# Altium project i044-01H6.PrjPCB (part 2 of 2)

## Sheet M_SSD128_HD_8_95Vin_5Vout_1500mA_LowProfile.SchDoc
size A4; Organization: Ingenia Drives - Novanta; Address1: Carrer Avila, 124, 2B; Address2: 08018 Barcelona Spain; Address3: www.ingeniamc.com; Address4: www.ingeniamc.com; DocumentNumber: 8; Revision: i044-01H6-1.2.3; SheetNumber: 8; SheetTotal: 8
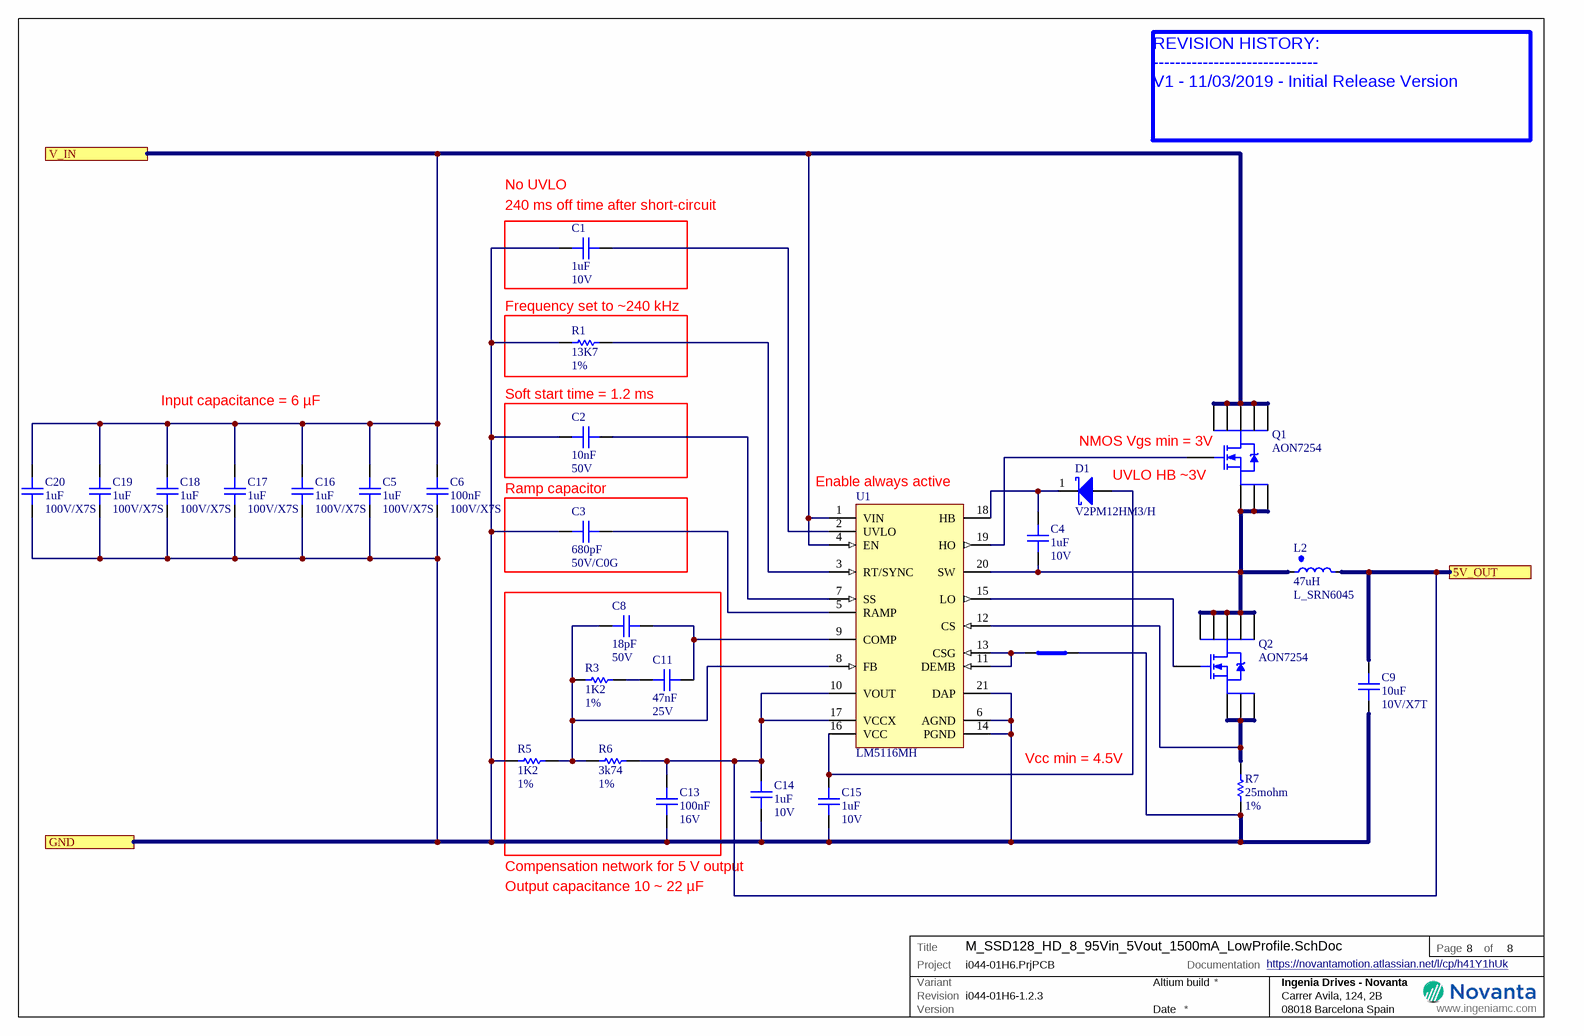
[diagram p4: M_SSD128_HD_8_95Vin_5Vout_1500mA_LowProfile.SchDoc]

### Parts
(Parts that share a designator on the sheet are numbered #1, #2 ... from top to bottom, then left to right.)
C1#2  value 1uF  Voltage: 10V  [C_0402HD]  (hidden comment: C_0402--1uF--10V)
C2#2  value 10nF  Voltage: 50V  [C_0402HD]  (hidden comment: C_0402--10nF--50V)
C3#2  value 680pF  Voltage: 50V/C0G  [C_0402HD]  (hidden comment: C_0402--680pF--50V/C0G)
C4#2  value 1uF  Voltage: 10V  [C_0402HD]  (hidden comment: C_0402--1uF--10V)
C5#2  value 1uF  Voltage: 100V/X7S  [C_0805_1.45mm]  (hidden comment: C_0805--1uF--100V/X7S)
C6#2  value 100nF  Voltage: 100V/X7S  [C_0603]  (hidden comment: C_0603--100nF--100V/X7S)
C8#2  value 18pF  Voltage: 50V  [C_0402HD]  (hidden comment: C_0402--18pF--50V)
C9#2  value 10uF  Voltage: 10V/X7T  [C_0603]  (hidden comment: C_0603--10uF--10V/X7T)
C11#2  value 47nF  Voltage: 25V  [C_0402HD]  (hidden comment: C_0402--47nF--25V)
C13#2  value 100nF  Voltage: 16V  [C_0402HD]  (hidden comment: C_0402--100nF--16V)
C14#2  value 1uF  Voltage: 10V  [C_0402HD]  (hidden comment: C_0402--1uF--10V)
C15#2  value 1uF  Voltage: 10V  [C_0402HD]  (hidden comment: C_0402--1uF--10V)
C16#2  value 1uF  Voltage: 100V/X7S  [C_0805_1.45mm]  (hidden comment: C_0805--1uF--100V/X7S)
C17#2  value 1uF  Voltage: 100V/X7S  [C_0805_1.45mm]  (hidden comment: C_0805--1uF--100V/X7S)
C18  value 1uF  Voltage: 100V/X7S  [C_0805_1.45mm]  (hidden comment: C_0805--1uF--100V/X7S)
C19#2  value 1uF  Voltage: 100V/X7S  [C_0805_1.45mm]  (hidden comment: C_0805--1uF--100V/X7S)
C20  value 1uF  Voltage: 100V/X7S  [C_0805_1.45mm]  (hidden comment: C_0805--1uF--100V/X7S)
D1#2  V2PM12HM3/H  [MicroSMP]
L2#2  value 47uH  [L_SRN6045]  (hidden comment: L_SRN6045--47uH)
NT1  NT_TOP_1.2x0.2  [NETTIE-TOP]  (value not drawn)  (net tie, no BOM)
Q1#2  AON7254  [8-PowerWDFN(3.3x3.3)]
Q2#2  AON7254  [8-PowerWDFN(3.3x3.3)]
R1#2  value 13K7  Tolerance: 1%  [R_0402HD]  (hidden comment: R_0402--13K7--1%)
R3#2  value 1K2  Tolerance: 1%  [R_0402HD]  (hidden comment: R_0402--1K2--1%)
R5#2  value 1K2  Tolerance: 1%  [R_0402HD]  (hidden comment: R_0402--1K2--1%)
R6#2  value 3k74  Tolerance: 1%  [R_0402HD]  (hidden comment: R_0402--3k74--1%)
R7#2  value 25mohm  Tolerance: 1%  [R_0603]  (hidden comment: R_0603--25mohm--1%)
U1#2  LM5116MH  [TSOP20_065P_EP]

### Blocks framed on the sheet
240 ms off time after short-circuit: C1#2
Frequency set to ~240 kHz: R1#2
Soft start time = 1.2 ms: C2#2
Ramp capacitor: C3#2

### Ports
5V_OUT, GND, V_IN

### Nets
5V_DCDC: C9#2.2 C13#2.1 C14#2.2 L2#2.2 R6#2.1 U1#2.10(VOUT) U1#2.17(VCCX) ; port 5V_OUT
+LOGIC_DCDC: C5#2.1 C6#2.2 C16#2.2 C17#2.1 C18.2 C19#2.2 C20.2 Q1#2.5(D) Q1#2.6(D) Q1#2.7(D) Q1#2.8(D) Q1#2.9(D) U1#2.1(VIN) U1#2.4(EN) ; port V_IN
GND_DCDC: C1#2.1 C2#2.1 C3#2.2 C5#2.2 C6#2.1 C9#2.1 C13#2.2 C14#2.1 C15#2.1 C16#2.1 C17#2.2 C18.1 C19#2.1 C20.1 NT1.2(Net2) R1#2.2 R5#2.2 R7#2.1 U1#2.6(AGND) U1#2.14(PGND) U1#2.21(DAP) ; port GND
NetC1#2_2: C1#2.2 U1#2.2(UVLO)
NetC2#2_2: C2#2.2 U1#2.7(SS)
NetC3#2_1: C3#2.1 U1#2.5(RAMP)
NetC4#2_1: C4#2.1 L2#2.1 Q1#2.1(S) Q1#2.2(S) Q1#2.3(S) Q2#2.5(D) Q2#2.6(D) Q2#2.7(D) Q2#2.8(D) Q2#2.9(D) U1#2.20(SW)
NetC4#2_2: C4#2.2 D1#2.1(K) U1#2.18(HB)
NetC8#2_1: C8#2.1 R3#2.2 R5#2.1 R6#2.2 U1#2.8(FB)
NetC8#2_2: C8#2.2 C11#2.2 U1#2.9(COMP)
NetC11#2_1: C11#2.1 R3#2.1
NetC15#2_2: C15#2.2 D1#2.2(A) U1#2.16(VCC)
NetNT1_1: NT1.1(Net1) U1#2.11(DEMB) U1#2.13(CSG)
NetQ1#2_4: Q1#2.4(G) U1#2.19(HO)
NetQ2#2_1: Q2#2.1(S) Q2#2.2(S) Q2#2.3(S) R7#2.2 U1#2.12(CS)
NetQ2#2_4: Q2#2.4(G) U1#2.15(LO)
NetR1#2_1: R1#2.1 U1#2.3(RT/SYNC)

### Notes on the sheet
- REVISION HISTORY:
  ------------------------------
  V1 - 11/03/2019 - Initial Release Version
- No UVLO
- Input capacitance = 6 µF
- (near Q1#2) NMOS Vgs min = 3V
- (near U1#2) Enable always active
- UVLO HB ~3V
- Vcc min = 4.5V
- Compensation network for 5 V output
- Output capacitance 10 ~ 22 µF
- https://novantamotion.atlassian.net/l/cp/h41Y1hUk

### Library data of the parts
C1#2 = C_0402[[/\]]1uF[[/\]]10V: Capacitor 1uF 10V Ceramic X7S 0402; Part Number: C_0402; ManufacturerName: TDK Corporation; ManufacturerPN: C1005X7S1A105K050BC; AlternativeManufacturer: Murata; IsPreferred: 0; IngeniaID: 1513; IsGeneric: 1; AlternativePN: GCM155C71A105KE38D; MTBF55h: 28045508; TemperatureMaxC: 125; TemperatureMinC: -55
C2#2 = C_0402[[/\]]10nF[[/\]]50V: CAP CER 10nF 50V X7R 0402; Part Number: C_0402; ManufacturerName: KEMET; ManufacturerPN: C0402C103K5RACTU; AlternativeManufacturer: TDK Corporation; IsPreferred: 0; IngeniaID: 3723; AlternativePN: C1005X8R1H103K050BB; TemperatureMaxC: 125; TemperatureMinC: -55
C3#2 = C_0402[[/\]]680pF[[/\]]50V/C0G: CAP CER 680pF 50V C0G 5% 0402; Part Number: C_0402; ManufacturerName: Murata; ManufacturerPN: GCM1555C1H681JA16D; IsPreferred: 0; IngeniaID: 2989; IsGeneric: 1; TemperatureMaxC: 125; TemperatureMinC: -55; AlternativePN: GCM1555C1H681FA16D
C4#2 C14#2 C15#2 = C_0402[[/\]]1uF[[/\]]10V: Capacitor 1uF 10V Ceramic X7S 0402; Part Number: C_0402; ManufacturerName: TDK Corporation; ManufacturerPN: C1005X7S1A105K050BC; AlternativeManufacturer: Murata; IsPreferred: 0; IngeniaID: 1513; IsGeneric: 1; TemperatureMaxC: 125; TemperatureMinC: -55; MTBF55h: 28045508; AlternativePN: GCM155C71A105KE38D
C5#2 C16#2 C17#2 C18 C19#2 C20 = C_0805[[/\]]1uF[[/\]]100V/X7S: MLCC, 1uF 100V X7S Boardflex 1.45mm max height; Part Number: C_0805; ManufacturerName: TDK Corporation; ManufacturerPN: C2012X7S2A105K125AE; IsPreferred: 1; IngeniaID: 2972; InternalStock: 0; TemperatureMaxC: 125; TemperatureMinC: -55; MTBF55h: 28045508; AlternativePN: C2012X7S2A105M125AE; AdditionalInformation: Height, is important, do not choose alternative capacitors with >1.45 mm
C6#2 = C_0603[[/\]]100nF[[/\]]100V/X7S: CAP CER 100nF 100V X7S 0603 0.8mm MAX height; ManufacturerName: TDK Corporation; ManufacturerPN: CGJ3E3X7S2A104K080AA; IsPreferred: 0; IngeniaID: 2977; TemperatureMaxC: 125; TemperatureMinC: -55; AlternativePN: CGA3E3X7S2A104K080AB
C8#2 = C_0402[[/\]]18pF[[/\]]50V: CAP CER 18pF 50V C0G 0402; Part Number: C_0402; ManufacturerName: Yageo; ManufacturerPN: CC0402FRNPO9BN180; AlternativeManufacturer: Samsung ElectroMechanics; IsPreferred: 1; IngeniaID: 675; InternalStock: 0; TemperatureMaxC: 125; TemperatureMinC: -55; MTBF55h: 93278882; AlternativePN: CL05C180GB5NCNC
C9#2 = C_0603[[/\]]10uF[[/\]]10V/X7T: CAP CER 10uF 10V X7T 0603 0.8mm MAX height; ManufacturerName: Murata; ManufacturerPN: GRM188D71A106MA73D; AlternativeManufacturer: Murata Electronics North America; IsPreferred: 0; IngeniaID: 2978; AlternativePN: GRM188D71A106KA73D; MTBF55h: 21770245; TemperatureMaxC: 125; TemperatureMinC: -55
C11#2 = C_0402[[/\]]47nF[[/\]]25V: CAP CER 47nF 25V X7R 10% 0402; Part Number: C_0402; ManufacturerName: TAIYO YUDEN; ManufacturerPN: TMK105B7473KV-F; AlternativeManufacturer: TDK Corporation; IsPreferred: 0; IngeniaID: 2329; IsGeneric: 1; AlternativePN: CGJ2B2X7R1E473K050BA; TemperatureMaxC: 125; TemperatureMinC: -55
C13#2 = C_0402[[/\]]100nF[[/\]]16V: CAP CER 100nF 16V X7R 0402; Part Number: C_0402; ManufacturerName: Murata; ManufacturerPN: GRM155R71C104KA88D; AlternativeManufacturer: Wurth; IsPreferred: 0; IngeniaID: 672; IsGeneric: 1; AlternativePN: 885012205037; TemperatureMaxC: 125; TemperatureMinC: -55
D1#2 = V2PM12HM3/H: DIODE SCHOTTKY 120V 2A MICROSMP; ManufacturerName: Vishay; IsGeneric: 0; TemperatureMaxC: 175; TemperatureMinC: -40; AlternativePN: V2PM12-M3/H
L2#2 = L_SRN6045[[/\]]47uH: INDUCTOR, 47uH 20%, 200mohm DCR, 1.6A rating 2A saturation, 6mmx6mm semi-shielded; ManufacturerName: Bourns; ManufacturerPN: SRN6045TA-470M; IsPreferred: 1; IngeniaID: 4415; InternalStock: 0; TemperatureMaxC: 125; TemperatureMinC: -55
NT1 = NT_TOP_1.2x0.2: Net-Tie, Surface Mount, 1.2mm x 0.2mm; IsPreferred: 0
Q1#2 Q2#2 = AON7254: MOSFET N-CH 150V 17A 8DFN 54mOhm Low Vgsth; ManufacturerName: Alpha & Omega Semiconductor Inc.; IsPreferred: 0; IngeniaID: 3191; TemperatureMaxC: 150; TemperatureMinC: -55
R1#2 = R_0402[[/\]]13K7[[/\]]1%: Resistor 0402 13K7 1%, 0.063W; Part Number: R_0402; ManufacturerName: Stackpole electronics; ManufacturerPN: RMCF0402FT13K7; AlternativeManufacturer: KOA Speer Electronics, Inc.; IsPreferred: 0; IngeniaID: 3587; IsGeneric: 1; TemperatureMaxC: 155; TemperatureMinC: -55; AlternativePN: RK73H1ETTP1372F
R3#2 = R_0402[[/\]]1K2[[/\]]1%: RES 1K2 OHM 1/16W 1% 0402 SMD; Part Number: R_0402; ManufacturerName: Yageo; ManufacturerPN: RC0402FR-071K2L; AlternativeManufacturer: Samsung Electro-Mechanics; IsPreferred: 1; IngeniaID: 1493; InternalStock: 0; TemperatureMaxC: 155; TemperatureMinC: -55; AlternativePN: RC1005F122CS
R5#2 = R_0402[[/\]]1K2[[/\]]1%: RES 1K2 OHM 1/16W 1% 0402 SMD; Part Number: R_0402; ManufacturerName: Yageo; ManufacturerPN: RC0402FR-071K2L; AlternativeManufacturer: Samsung Electro-Mechanics; IsPreferred: 1; IngeniaID: 1493; InternalStock: 0; AlternativePN: RC1005F122CS; TemperatureMaxC: 155; TemperatureMinC: -55
R6#2 = R_0402[[/\]]3k74[[/\]]1%: Resistor 0402 3k74 1%, 0.063W; Part Number: R_0402; ManufacturerName: Vishay Dale; ManufacturerPN: CRCW04023K74FKED; AlternativeManufacturer: Yageo; IsPreferred: 0; IngeniaID: 2330; IsGeneric: 1; AlternativePN: RC0402FR-073K74L; TemperatureMaxC: 155; TemperatureMinC: -55
R7#2 = R_0603[[/\]]25mohm[[/\]]1%: Resistor 0.025ohm 330mW 1% high power thick film; ManufacturerName: Panasonic; ManufacturerPN: ERJ-3BWFR025V; IsPreferred: 1; IngeniaID: 4402; InternalStock: 0; TemperatureMaxC: 155; TemperatureMinC: -55; AlternativePN: ERJ-3BWJR025V
U1#2 = LM5116MH: 100V DC/DC controller, buck synchronous; ManufacturerName: Texas Instruments; ManufacturerPN: LM5116MH/NOPB; IsPreferred: 1; IngeniaID: 716; InternalStock: 0; AlternativePN: LM5116MHX/NOPB; TemperatureMaxC: 125; TemperatureMinC: -40

## Sheet M_ICA011_HDI_CAN_Interface_NonIsolated_5Vsupply.SchDoc
size A4; Organization: Ingenia Drives - Novanta; Address1: Carrer Avila, 124, 2B; Address2: 08018 Barcelona Spain; Address3: www.ingeniamc.com; Address4: www.ingeniamc.com; DocumentNumber: 4; Revision: i044-01H6-1.2.3; SheetNumber: 4; SheetTotal: 8
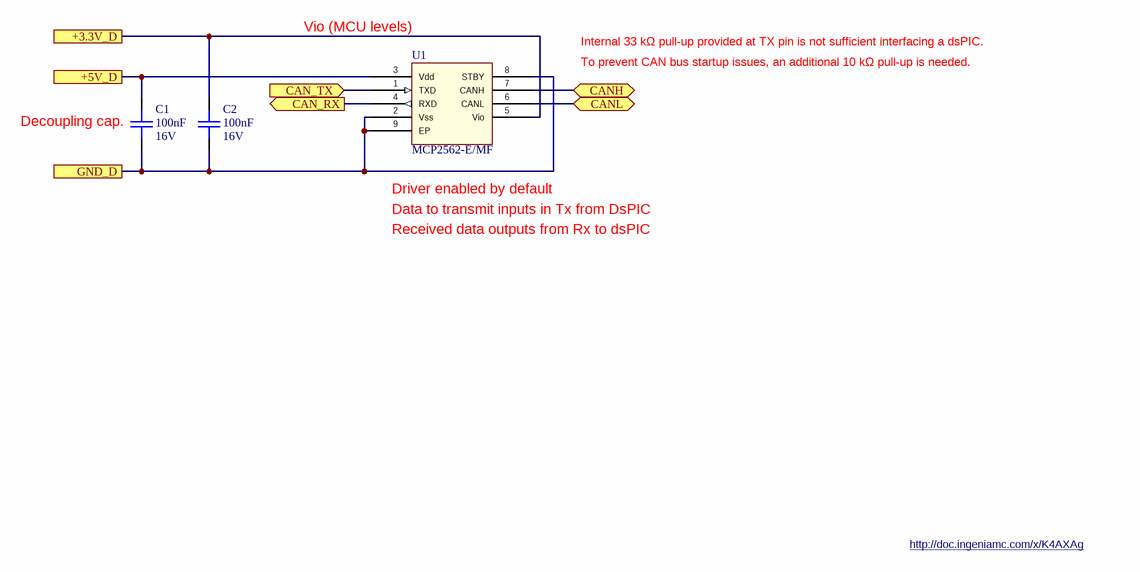
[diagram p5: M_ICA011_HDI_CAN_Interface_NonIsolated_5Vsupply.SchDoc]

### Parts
(Parts that share a designator on the sheet are numbered #1, #2 ... from top to bottom, then left to right.)
C1#3  value 100nF  Voltage: 16V  [C_0402HD]  (hidden comment: C_0402--100nF--16V)
C2#3  value 100nF  Voltage: 16V  [C_0402HD]  (hidden comment: C_0402--100nF--16V)
U1#3  MCP2562-E/MF  [DFN-8(3x3)]

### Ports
+3.3V_D, +5V_D, CAN_RX (out), CAN_TX (in), CANH (bidir), CANL (bidir), GND_D

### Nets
5V_D: C1#3.2 U1#3.3(Vdd) ; port +5V_D
GND_D: C1#3.1 C2#3.1 U1#3.2(Vss) U1#3.8(STBY) U1#3.9(EP) ; port GND_D
3.3V_D: C2#3.2 U1#3.5(Vio) ; port +3.3V_D
CAN_COCO_RX: U1#3.4(RXD) ; port CAN_RX
CAN_COCO_TX: U1#3.1(TXD) ; port CAN_TX
CANH: U1#3.7(CANH) ; port CANH
CANL: U1#3.6(CANL) ; port CANL

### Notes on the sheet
- (near U1#3) Vio (MCU levels)
- Internal 33 kΩ pull-up provided at TX pin is not sufficient interfacing a dsPIC.
- To prevent CAN bus startup issues, an additional 10 kΩ pull-up is needed.
- (near C1#3) Decoupling cap.
- (near U1#3) Driver enabled by default
- Data to transmit inputs in Tx from DsPIC
- Received data outputs from Rx to dsPIC
- http://doc.ingeniamc.com/x/K4AXAg

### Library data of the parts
C1#3 C2#3 = C_0402[[/\]]100nF[[/\]]16V: as C13#2 on sheet M_SSD128_HD_8_95Vin_5Vout_1500mA_LowProfile
U1#3 = MCP2562-E/MF: (NRND) CAN Transceiver 1Mbps 8DFN (3x3); ManufacturerName: MICROCHIP; IsPreferred: 0; IngeniaID: 2095; AlternativePN: MCP2562T-E/MF; TemperatureMaxC: 125; TemperatureMinC: -40; AdditionalInformation: Marked as NRND by Microchip. Direct substitute is MCP2562FDT

## Sheet M_PXE032_HD_Diff-SE_Digital_Abs_Encoder_WBias_WTerm.SchDoc
size A4; Organization: Ingenia Drives - Novanta; Address1: Carrer Avila, 124, 2B; Address2: 08018 Barcelona Spain; Address3: www.ingeniamc.com; Address4: www.ingeniamc.com; DocumentNumber: 7; Revision: i044-01H6-1.2.3; SheetNumber: 7; SheetTotal: 8
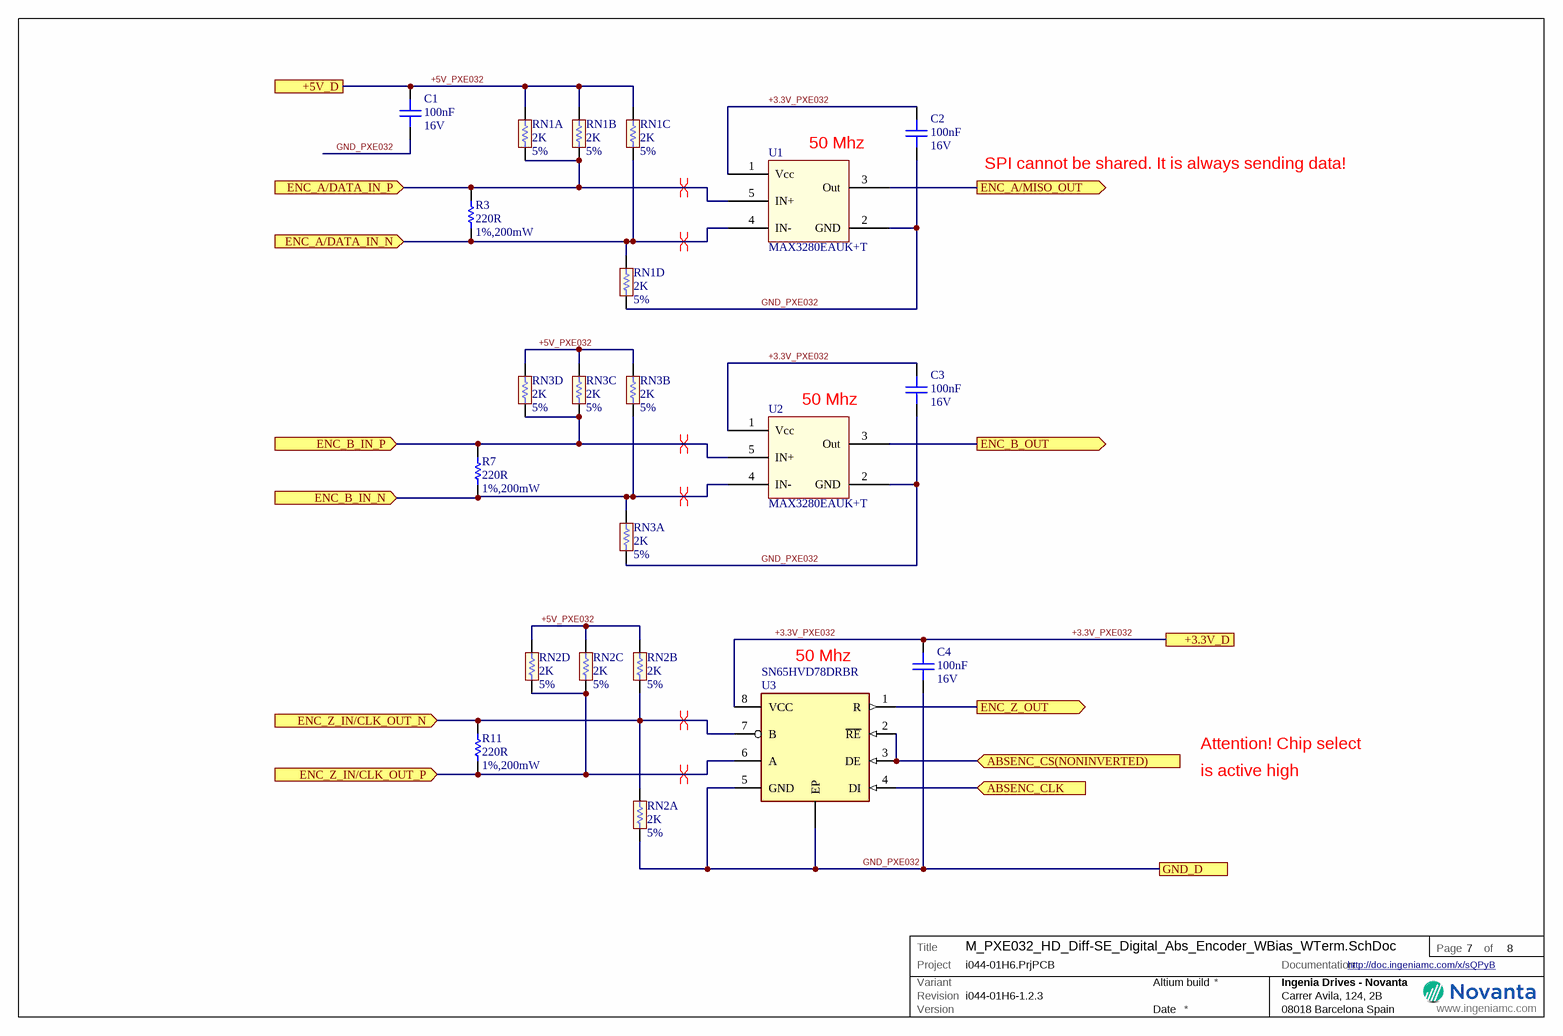
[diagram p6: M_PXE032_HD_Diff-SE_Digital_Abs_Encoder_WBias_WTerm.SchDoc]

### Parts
(Parts that share a designator on the sheet are numbered #1, #2 ... from top to bottom, then left to right.)
C1#4  value 100nF  Voltage: 16V  [C_0402HD]  (hidden comment: C_0402--100nF--16V)
C2#4  value 100nF  Voltage: 16V  [C_0402HD]  (hidden comment: C_0402--100nF--16V)
C3#3  value 100nF  Voltage: 16V  [C_0402HD]  (hidden comment: C_0402--100nF--16V)
C4#3  value 100nF  Voltage: 16V  [C_0402HD]  (hidden comment: C_0402--100nF--16V)
R3#3  value 220R  Tolerance: 1%,200mW  [R_0402HD]  (hidden comment: R_0402--220R--1%,200mW)
R7#3  value 220R  Tolerance: 1%,200mW  [R_0402HD]  (hidden comment: R_0402--220R--1%,200mW)
R11#2  value 220R  Tolerance: 1%,200mW  [R_0402HD]  (hidden comment: R_0402--220R--1%,200mW)
RN1#1  value 2K  Tolerance: 5%  [R_ARR_CRA04S08]  (hidden comment: R_ARRAY_0804_8--2K--5%)  (parts A,B,C,D of 4)
RN2#2  value 2K  Tolerance: 5%  [R_ARR_CRA04S08]  (hidden comment: R_ARRAY_0804_8--2K--5%)  (parts A,B,C,D of 4)
RN3#2  value 2K  Tolerance: 5%  [R_ARR_CRA04S08]  (hidden comment: R_ARRAY_0804_8--2K--5%)  (parts A,B,C,D of 4)
U1#4  MAX3280EAUK+T  [SOT23-5N]
U2#2  MAX3280EAUK+T  [SOT23-5N]
U3#2  SN65HVD78DRBR  [VSON-8_(DFN-8)_NoVias]

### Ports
+3.3V_D, +5V_D, ABSENC_CLK (in), ABSENC_CS(NONINVERTED) (in), ENC_A/DATA_IN_N (in), ENC_A/DATA_IN_P (in), ENC_A/MISO_OUT (out), ENC_B_IN_N (in), ENC_B_IN_P (in), ENC_B_OUT (out), ENC_Z_IN/CLK_OUT_N (in), ENC_Z_IN/CLK_OUT_P (in), ENC_Z_OUT (out), GND_D

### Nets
+5V_PXE032: C1#4.1 RN1#1.2 RN1#1.4 RN1#1.6 RN2#2.4 RN2#2.6 RN2#2.8 RN3#2.4 RN3#2.6 RN3#2.8 ; port +5V_D  [project net 5V_D]
GND_PXE032: C1#4.2 C2#4.2 C3#3.2 C4#3.2 RN1#1.8 RN2#2.2 RN3#2.2 U1#4.2(GND) U2#2.2(GND) U3#2.0(EP) U3#2.5(GND) ; port GND_D  [project net GND_D]
+3.3V_PXE032: C2#4.1 C3#3.1 C4#3.1 U1#4.1(Vcc) U2#2.1(Vcc) U3#2.8(VCC) ; port +3.3V_D  [project net 3.3V_D]
ABS2_CS: U3#2.2(~{RE}) U3#2.3(DE) ; port ABSENC_CS(NONINVERTED)
ABSENC2_CLK: U3#2.4(DI) ; port ABSENC_CLK
ABSENC2_MISO/DIGENC_1A: U1#4.3(Out) ; port ENC_A/MISO_OUT
DIG_ENC_1B: U2#2.3(Out) ; port ENC_B_OUT
DIG_ENC_1C/AN_ENC_1C: U3#2.1(R) ; port ENC_Z_OUT
ENC_A/DATA_IN_N: R3#3.1 RN1#1.5 RN1#1.7 U1#4.4(IN-) ; port ENC_A/DATA_IN_N
ENC_A/DATA_IN_P: R3#3.2 RN1#1.1 RN1#1.3 U1#4.5(IN+) ; port ENC_A/DATA_IN_P
ENC_B_IN_N: R7#3.1 RN3#2.1 RN3#2.3 U2#2.4(IN-) ; port ENC_B_IN_N
ENC_B_IN_P: R7#3.2 RN3#2.5 RN3#2.7 U2#2.5(IN+) ; port ENC_B_IN_P
ENC_Z_IN/CLK_OUT_N: R11#2.2 RN2#2.1 RN2#2.3 U3#2.7(B) ; port ENC_Z_IN/CLK_OUT_N
ENC_Z_IN/CLK_OUT_P: R11#2.1 RN2#2.5 RN2#2.7 U3#2.6(A) ; port ENC_Z_IN/CLK_OUT_P

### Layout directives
differential pair: ENC_A/DATA_IN_N, ENC_A/DATA_IN_P, ENC_B_IN_N, ENC_B_IN_P, ENC_Z_IN/CLK_OUT_N, ENC_Z_IN/CLK_OUT_P

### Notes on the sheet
- (near U1#4) 50 Mhz
- SPI cannot be shared. It is always sending data!
- (near U2#2) 50 Mhz
- (near U3#2) 50 Mhz
- Attention! Chip select
- is active high
- http://doc.ingeniamc.com/x/sQPyB

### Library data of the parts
C1#4 C2#4 C3#3 C4#3 = C_0402[[/\]]100nF[[/\]]16V: as C13#2 on sheet M_SSD128_HD_8_95Vin_5Vout_1500mA_LowProfile
R3#3 R7#3 R11#2 = R_0402[[/\]]220R[[/\]]1%,200mW: Resistor 220ohm 200mW high power pulse withstanding; Part Number: R_0402; ManufacturerName: Panasonic Electronic Components; ManufacturerPN: ERJ-PA2F2200X; AlternativeManufacturer: VISHAY; IsPreferred: 0; IsGeneric: 1; IngeniaID: 3040; AlternativePN: CRCW0402220RFKEDHP; TemperatureMaxC: 155; TemperatureMinC: -55
RN1#1 RN2#2 RN3#2 = R_ARRAY_0804_8[[/\]]2K[[/\]]5%: RESISTOR ARRAY4 2k 1/16W 5%; ManufacturerName: Vishay Dale; ManufacturerPN: CRA04S0832K00JTD; AlternativeManufacturer: Panasonic; IsPreferred: 0; IngeniaID: 1503; IsGeneric: 1; TemperatureMaxC: 155; TemperatureMinC: -55; AlternativePN: EXB-28V202JX
U1#4 U2#2 = MAX3280EAUK+T: Single differential line receiver RS422 RS485 52 MBps 125ºC; ManufacturerName: Maxim Integrated; IsPreferred: 1; IsGeneric: 0; IngeniaID: 2197; TemperatureMaxC: 125; TemperatureMinC: -40
U3#2 = SN65HVD78DRBR: RS-485/422 Transceiver (1 TX/ 1 RX), 50Mbps, 3.3V; ManufacturerName: Texas Instruments; IsPreferred: 0; IngeniaID: 4253; TemperatureMaxC: 125; TemperatureMinC: -40; AlternativePN: SN65HVD78DRBT

## Sheet M_IEA007_HDI_EtherNet_Discrete_Magnetics+ESD.SchDoc: ixxx
size A4; Organization: Ingenia Drives - Novanta; Address1: Carrer Avila, 124 2B; Address2: 08018 Barcelona Spain; Address3: www.ingeniamc.com; Address4: www.ingeniamc.com; DocumentNumber: 6; Revision: 4.0; SheetNumber: 6; SheetTotal: 15
Used 2 times, as channels U_M_IEA007_EHT0, U_M_IEA007_EHT1. Parts and nets are listed once, with the designators drawn on the sheet.
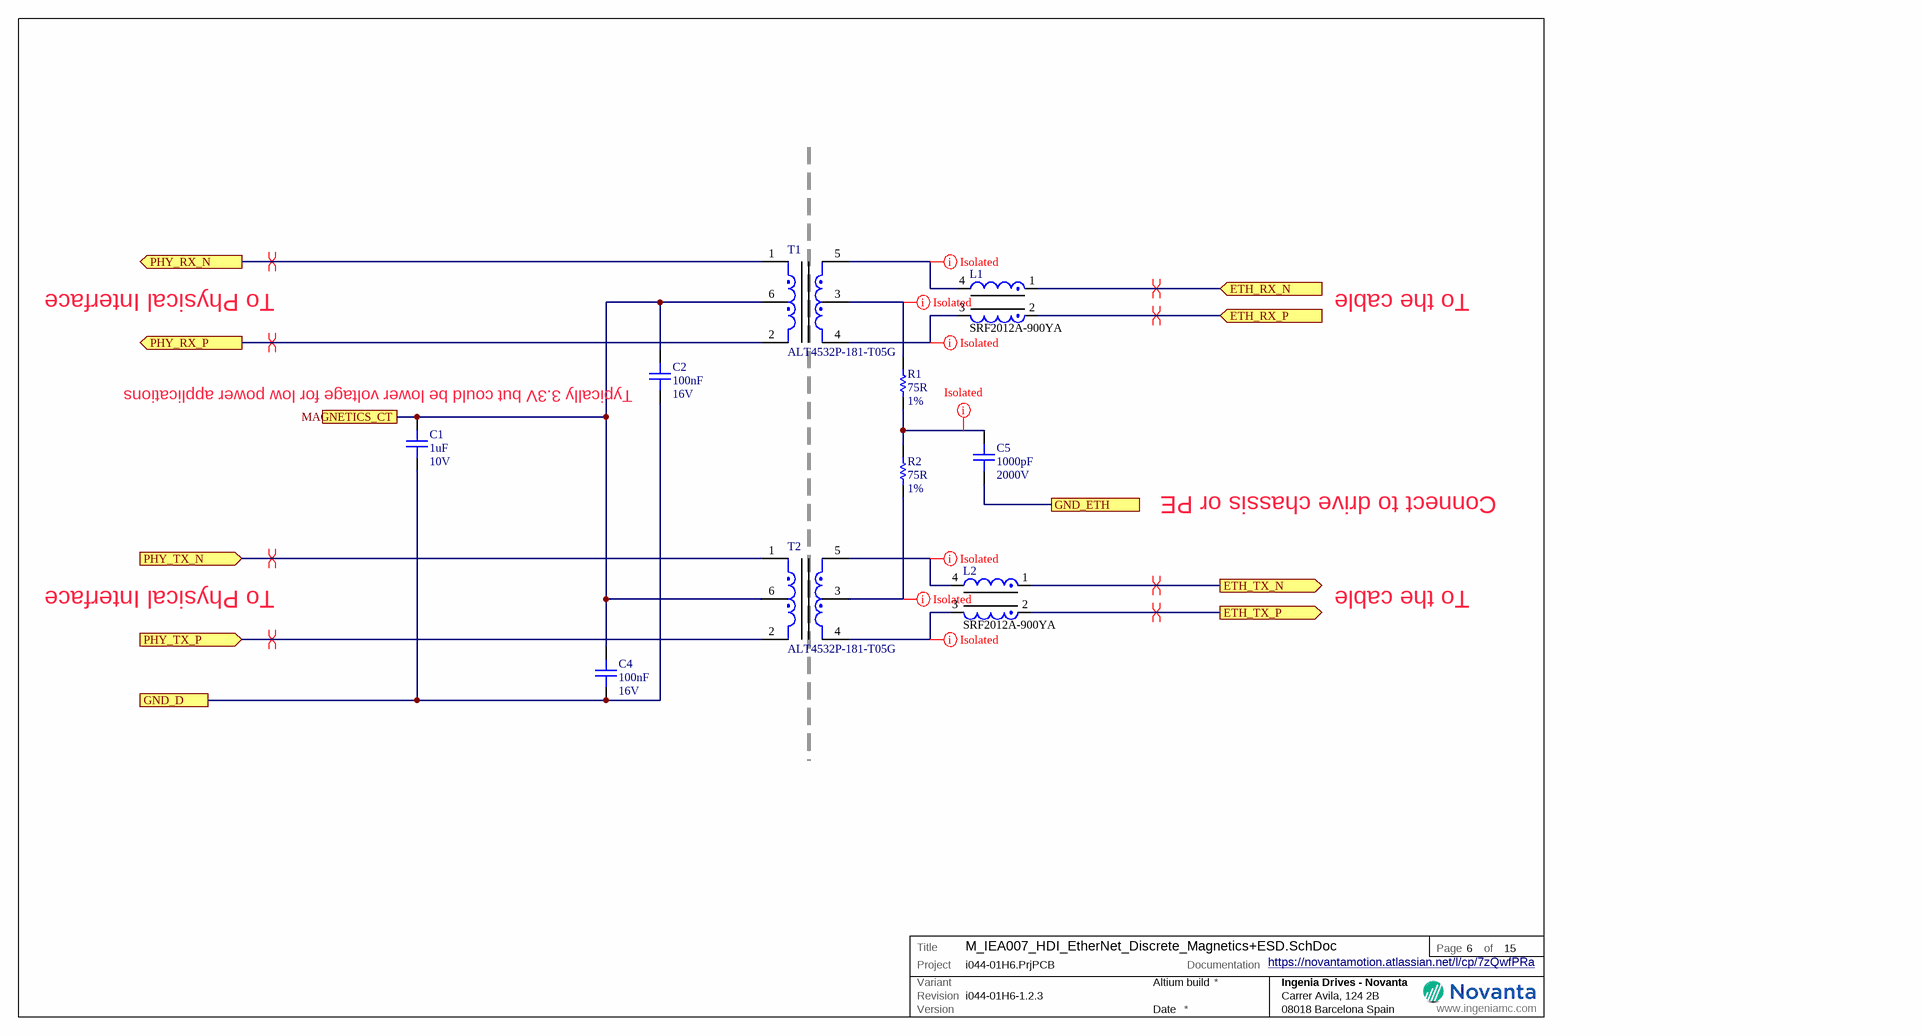
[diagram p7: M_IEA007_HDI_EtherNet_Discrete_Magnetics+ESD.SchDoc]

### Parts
C1  value 1uF  Voltage: 10V  [C_0402HD]  (hidden comment: C_0402--1uF--10V)
C2  value 100nF  Voltage: 16V  [C_0402HD]  (hidden comment: C_0402--100nF--16V)
C4  value 100nF  Voltage: 16V  [C_0402HD]  (hidden comment: C_0402--100nF--16V)
C5  value 1000pF  Voltage: 2000V  [C_1206]  (hidden comment: C_1206--1000pF--2000V)
L1  SRF2012A-900YA  [ACM2012E]
L2  SRF2012A-900YA  [ACM2012E]
R1  value 75R  Tolerance: 1%  [R_0402HD]  (hidden comment: R_0402--75R--1%)
R2  value 75R  Tolerance: 1%  [R_0402HD]  (hidden comment: R_0402--75R--1%)
T1  ALT4532P-181-T05G  [TDK_ALT4523]
T2  ALT4532P-181-T05G  [TDK_ALT4523]

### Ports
ETH_RX_N (in), ETH_RX_P (in), ETH_TX_N (out), ETH_TX_P (out), GND_D, GND_ETH, MAGNETICS_CT, PHY_RX_N (out), PHY_RX_P (out), PHY_TX_N (in), PHY_TX_P (in)

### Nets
ETH_RX_N: L1.1 ; port ETH_RX_N
ETH_RX_P: L1.2 ; port ETH_RX_P
ETH_TX_N: L2.1 ; port ETH_TX_N
ETH_TX_P: L2.2 ; port ETH_TX_P
GND_D: C1.1 C2.2 C4.2 ; port GND_D
GND_ETH: C5.1 ; port GND_ETH
MAGNETICS_CT: C1.2 C2.1 C4.1 T1.6(DCT) T2.6(DCT) ; port MAGNETICS_CT
PHY_RX_N: T1.1(D+) ; port PHY_RX_N
PHY_RX_P: T1.2(D-) ; port PHY_RX_P
PHY_TX_N: T2.1(D+) ; port PHY_TX_N
PHY_TX_P: T2.2(D-) ; port PHY_TX_P
NetC5_2: C5.2 R1.2 R2.1
NetL1_3: L1.3 T1.4(X-)
NetL1_4: L1.4 T1.5(X+)
NetL2_3: L2.3 T2.4(X-)
NetL2_4: L2.4 T2.5(X+)
NetR1_1: R1.1 T1.3(XCT)
NetR2_2: R2.2 T2.3(XCT)

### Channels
U_M_IEA007_EHT0: designators end in _U_M_IEA007_EHT0; ports ETH_RX_N=ETH0_RX_N ETH_RX_P=ETH0_RX_P ETH_TX_N=ETH0_TX_N ETH_TX_P=ETH0_TX_P GND_D=GND_D GND_ETH=PE1 MAGNETICS_CT=MAGNETICS_CT PHY_RX_N=PHY0_RX_N PHY_RX_P=PHY0_RX_P PHY_TX_N=PHY0_TX_N PHY_TX_P=PHY0_TX_P
U_M_IEA007_EHT1: designators end in _U_M_IEA007_EHT1; ports ETH_RX_N=ETH1_RX_N ETH_RX_P=ETH1_RX_P ETH_TX_N=ETH1_TX_N ETH_TX_P=ETH1_TX_P GND_D=GND_D GND_ETH=PE MAGNETICS_CT=MAGNETICS_CT PHY_RX_N=PHY1_RX_N PHY_RX_P=PHY1_RX_P PHY_TX_N=PHY1_TX_N PHY_TX_P=PHY1_TX_P

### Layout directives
differential pair: ETH0_RX_N, ETH0_RX_P, ETH0_TX_N, ETH0_TX_P, PHY0_RX_N, PHY0_RX_P, PHY0_TX_N, PHY0_TX_P
net class Iso: NetC5_U_M_IEA007_EHT0_2, NetL1_U_M_IEA007_EHT0_3, NetL1_U_M_IEA007_EHT0_4, NetL2_U_M_IEA007_EHT0_3, NetL2_U_M_IEA007_EHT0_4, NetR1_U_M_IEA007_EHT0_1, NetR2_U_M_IEA007_EHT0_2

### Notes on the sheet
- To Physical Interface
- To the cable
- Typically 3.3V but could be lower voltage for low power applications
- Connect to drive chassis or PE
- https://novantamotion.atlassian.net/l/cp/7zQwfPRa

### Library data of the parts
C1 = C_0402[[/\]]1uF[[/\]]10V: Capacitor 1uF 10V Ceramic X7S 0402; Part Number: C_0402; ManufacturerName: TDK Corporation; ManufacturerPN: C1005X7S1A105K050BC; AlternativeManufacturer: Murata; IsGeneric: 1; AlternativePN: GCM155C71A105KE38D; TemperatureMaxC: 125; TemperatureMinC: -55
C2 C4 = C_0402[[/\]]100nF[[/\]]16V: CAP CER 100nF 16V X7R 0402; Part Number: C_0402; ManufacturerName: Samsung Electro-Mechanics; ManufacturerPN: CL05B104KO5VPNC; AlternativeManufacturer: Wurth; IsGeneric: 1; AlternativePN: 885012205037; TemperatureMaxC: 125; TemperatureMinC: -55
C5 = C_1206[[/\]]1000pF[[/\]]2000V: CAP CERM 1000PF 2000V X7R; ManufacturerName: Knowles Syfer; ManufacturerPN: 1206Y2K00102KST; IsGeneric: 1; TemperatureMaxC: 125; TemperatureMinC: -55; AlternativePN: 1206Y2K00102KJT
L1 L2 = SRF2012A-900YA[[/\]]90Z: 2 Line 2 Line Common Mode Choke 125ºC 90Ohms 50V @100MHz 370mA DCR 300 mOhm for LAN; AlternativeManufacturer: Wurth; ManufacturerName: Bourns; AlternativePN: 744231091; CompletePN: SRF2012A-900YA--90Z; IsGeneric: 0; TemperatureMaxC: 125; TemperatureMinC: -40; Value: 90Z
R1 R2 = R_0402[[/\]]75R[[/\]]1%: RES 75 OHM 1/16W 1% 0402 SMD; Part Number: R_0402; ManufacturerName: Panasonic; ManufacturerPN: ERJ-2RKF75R0X; AlternativeManufacturer: Samsung; IsGeneric: 1; TemperatureMaxC: 155; TemperatureMinC: -55; AlternativePN: RC1005F750CS
T1 T2 = ALT4532P-181-T05G[[/\]]-: Pulse Transformer LAN 1CT:1CT 180µH 1000BASE-T/2.5GBASE-T/5GBASE-T, PoE[600mA]; ManufacturerName: TDK; CompletePN: ALT4532P-181-T05G---; IsGeneric: 0; TemperatureMaxC: 105; TemperatureMinC: -40

## Sheet M_PXA001_HDI_BiSS_SSI_EnDAT_AbsoluteEncoder.SchDoc
size A4; Organization: Ingenia Drives - Novanta; Address1: Carrer Avila, 124, 2B; Address2: 08018 Barcelona Spain; Address3: www.ingeniamc.com; Address4: www.ingeniamc.com; DocumentNumber: 6; Revision: i044-01H6-1.2.3; SheetNumber: 6; SheetTotal: 8
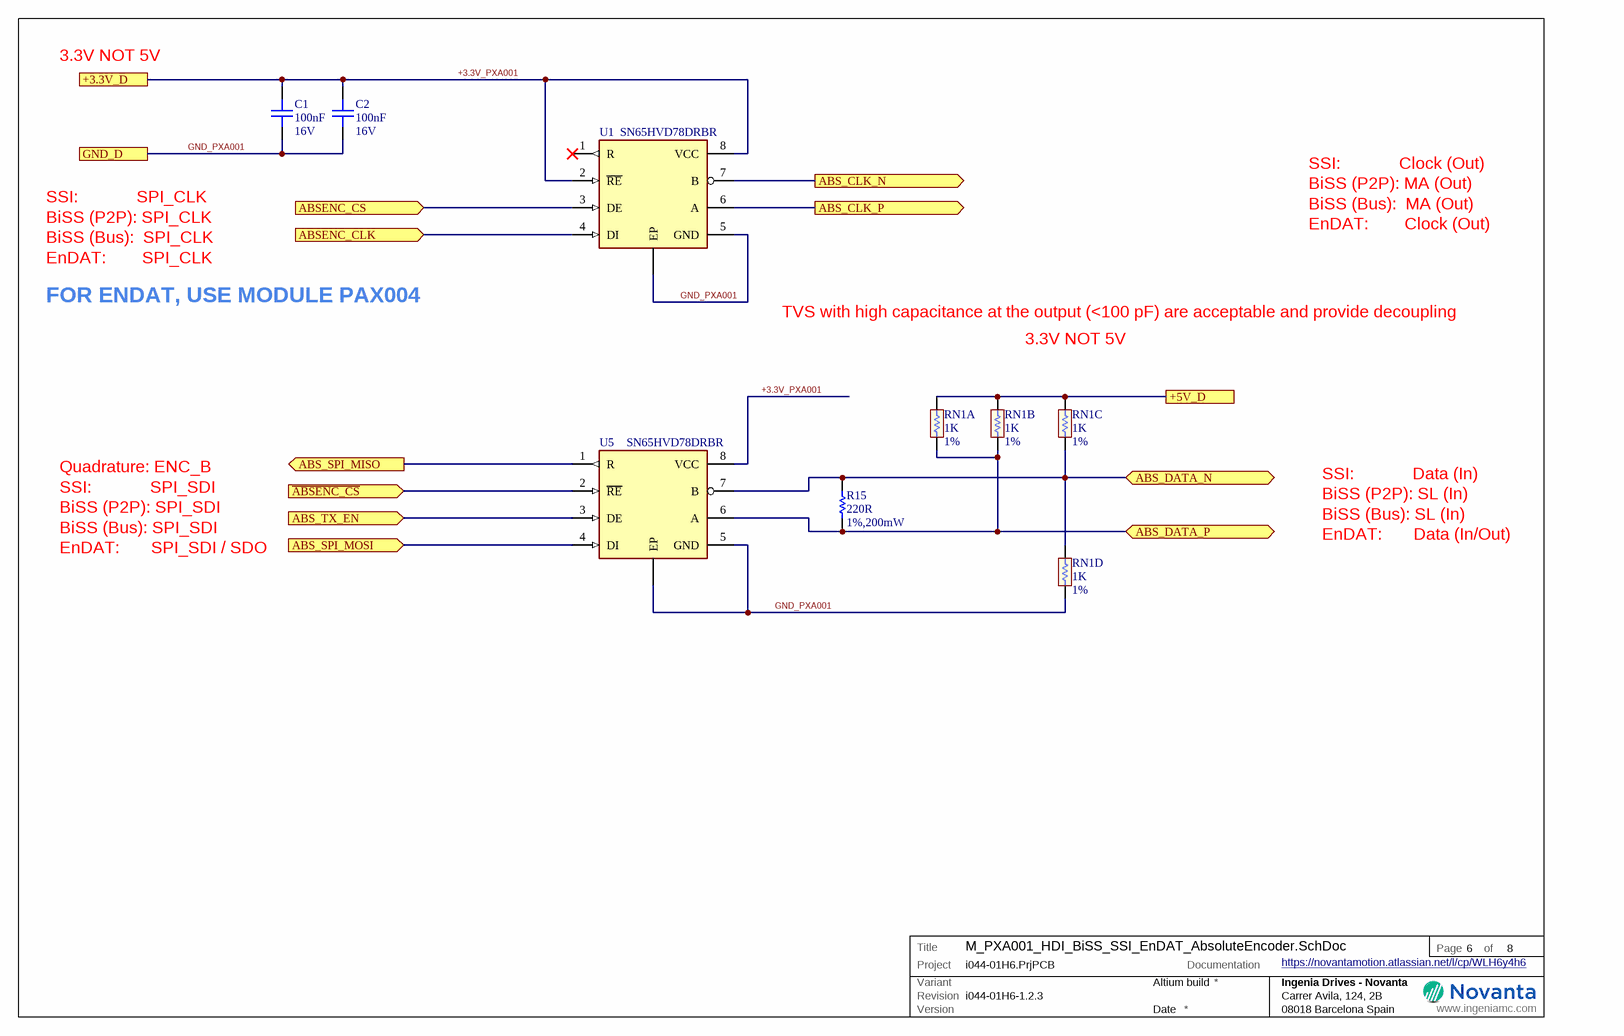
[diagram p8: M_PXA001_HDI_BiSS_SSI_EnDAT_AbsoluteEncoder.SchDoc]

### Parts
(Parts that share a designator on the sheet are numbered #1, #2 ... from top to bottom, then left to right.)
C1#5  value 100nF  Voltage: 16V  [C_0402HD]  (hidden comment: C_0402--100nF--16V)
C2#5  value 100nF  Voltage: 16V  [C_0402HD]  (hidden comment: C_0402--100nF--16V)
R15#2  value 220R  Tolerance: 1%,200mW  [R_0402HD]  (hidden comment: R_0402--220R--1%,200mW)
RN1#2  value 1K  Tolerance: 1%  [R_ARR_CRA04S08]  (hidden comment: R_ARRAY_0804_8--1K--1%)  (parts A,B,C,D of 4)
U1#5  SN65HVD78DRBR  [VSON-8_(DFN-8)_NoVias]
U5  SN65HVD78DRBR  [VSON-8_(DFN-8)_NoVias]

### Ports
+3.3V_D, +5V_D, ABS_CLK_N (out), ABS_CLK_P (out), ABS_DATA_N (bidir), ABS_DATA_P (bidir), ABS_SPI_MISO (out), ABS_SPI_MOSI (in), ABS_TX_EN (in), ABSENC_CLK (in), ABSENC_CS (in), GND_D, ~{ABSENC_CS} (in)

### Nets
5V_D: RN1#2.1 RN1#2.3 RN1#2.5 ; port +5V_D
GND_PXA001: C1#5.2 C2#5.2 RN1#2.7 U1#5.0(EP) U1#5.5(GND) U5.0(EP) U5.5(GND) ; port GND_D  [project net GND_D]
+3.3V_PXA001: C1#5.1 C2#5.1 U1#5.2(~{RE}) U1#5.8(VCC) U5.8(VCC) ; port +3.3V_D  [project net 3.3V_D]
~{ABSENC1_CS}: U5.2(~{RE}) ; port ~{ABSENC_CS}
ABS_SPI_CS: U1#5.3(DE) ; port ABSENC_CS
ABS_TX_EN: U5.3(DE) ; port ABS_TX_EN
ABSENC1_CLK: U1#5.4(DI) ; port ABSENC_CLK
ABSENC1_MISO: U5.4(DI) ; port ABS_SPI_MOSI
ABSENC1_MOSI: U5.1(R) ; port ABS_SPI_MISO
ABSENC_CLK_N: U1#5.7(B) ; port ABS_CLK_N
ABSENC_CLK_P: U1#5.6(A) ; port ABS_CLK_P
ABSENC_DATA_N: R15#2.2 RN1#2.6 RN1#2.8 U5.7(B) ; port ABS_DATA_N
ABSENC_DATA_P: R15#2.1 RN1#2.2 RN1#2.4 U5.6(A) ; port ABS_DATA_P

Not connected (* = marked no-connect by the designer): U1#5 1(R)*

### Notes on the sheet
- 3.3V NOT 5V
- SSI:             Clock (Out)
- SSI:             SPI_CLK
- BiSS (P2P): SPI_CLK
- BiSS (Bus):  SPI_CLK
- BiSS (P2P): MA (Out)
- BiSS (Bus):  MA (Out)
- EnDAT:        Clock (Out)
- EnDAT:        SPI_CLK
- FOR ENDAT, USE MODULE PAX004
- TVS with high capacitance at the output (<100 pF) are acceptable and provide decoupling
- Quadrature: ENC_B
- SSI:             SPI_SDI
- BiSS (P2P): SPI_SDI
- SSI:             Data (In)
- BiSS (P2P): SL (In)
- BiSS (Bus): SL (In)
- EnDAT:       SPI_SDI / SDO
- BiSS (Bus): SPI_SDI
- EnDAT:       Data (In/Out)
- https://novantamotion.atlassian.net/l/cp/WLH6y4h6

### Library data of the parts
C1#5 C2#5 = C_0402[[/\]]100nF[[/\]]16V: CAP CER 100nF 16V X7R 0402; Part Number: C_0402; ManufacturerName: Murata; ManufacturerPN: GRM155R71C104KA88D; AlternativeManufacturer: Wurth; IsPreferred: 0; IngeniaID: 672; IsGeneric: 1; TemperatureMaxC: 125; TemperatureMinC: -55; AlternativePN: 885012205037
R15#2 = R_0402[[/\]]220R[[/\]]1%,200mW: as R3#3 on sheet M_PXE032_HD_Diff-SE_Digital_Abs_Encoder_WBias_WTerm
RN1#2 = R_ARRAY_0804_8[[/\]]1K[[/\]]1%: RESISTOR ARRAY4 1k 1/16W 1%; ManufacturerName: Panasonic Electronic Components; ManufacturerPN: EXB-28V102JX; AlternativeManufacturer: Yageo; IsPreferred: 0; IngeniaID: 1502; IsGeneric: 1; TemperatureMaxC: 155; TemperatureMinC: -55; AlternativePN: YC124-JR-071KL; AdditionalInformation: 2nd alternative: RP104PJ102CS (Samsung Electro-Mechanics)
U1#5 U5 = SN65HVD78DRBR: as U3#2 on sheet M_PXE032_HD_Diff-SE_Digital_Abs_Encoder_WBias_WTerm

## Sheet M_FMS007_Optocoupled_input_STO_SIL3_Compliant.SchDoc: ixxx
size A3; Organization: Ingenia Drives - Novanta; Address1: Carrer Avila, 124, 2B; Address2: 08018 Barcelona Spain; Address3: www.ingeniamc.com; Address4: www.ingeniamc.com; DocumentNumber: 14; Revision: i044-01H6-1.2.3; SheetNumber: 14; SheetTotal: 15
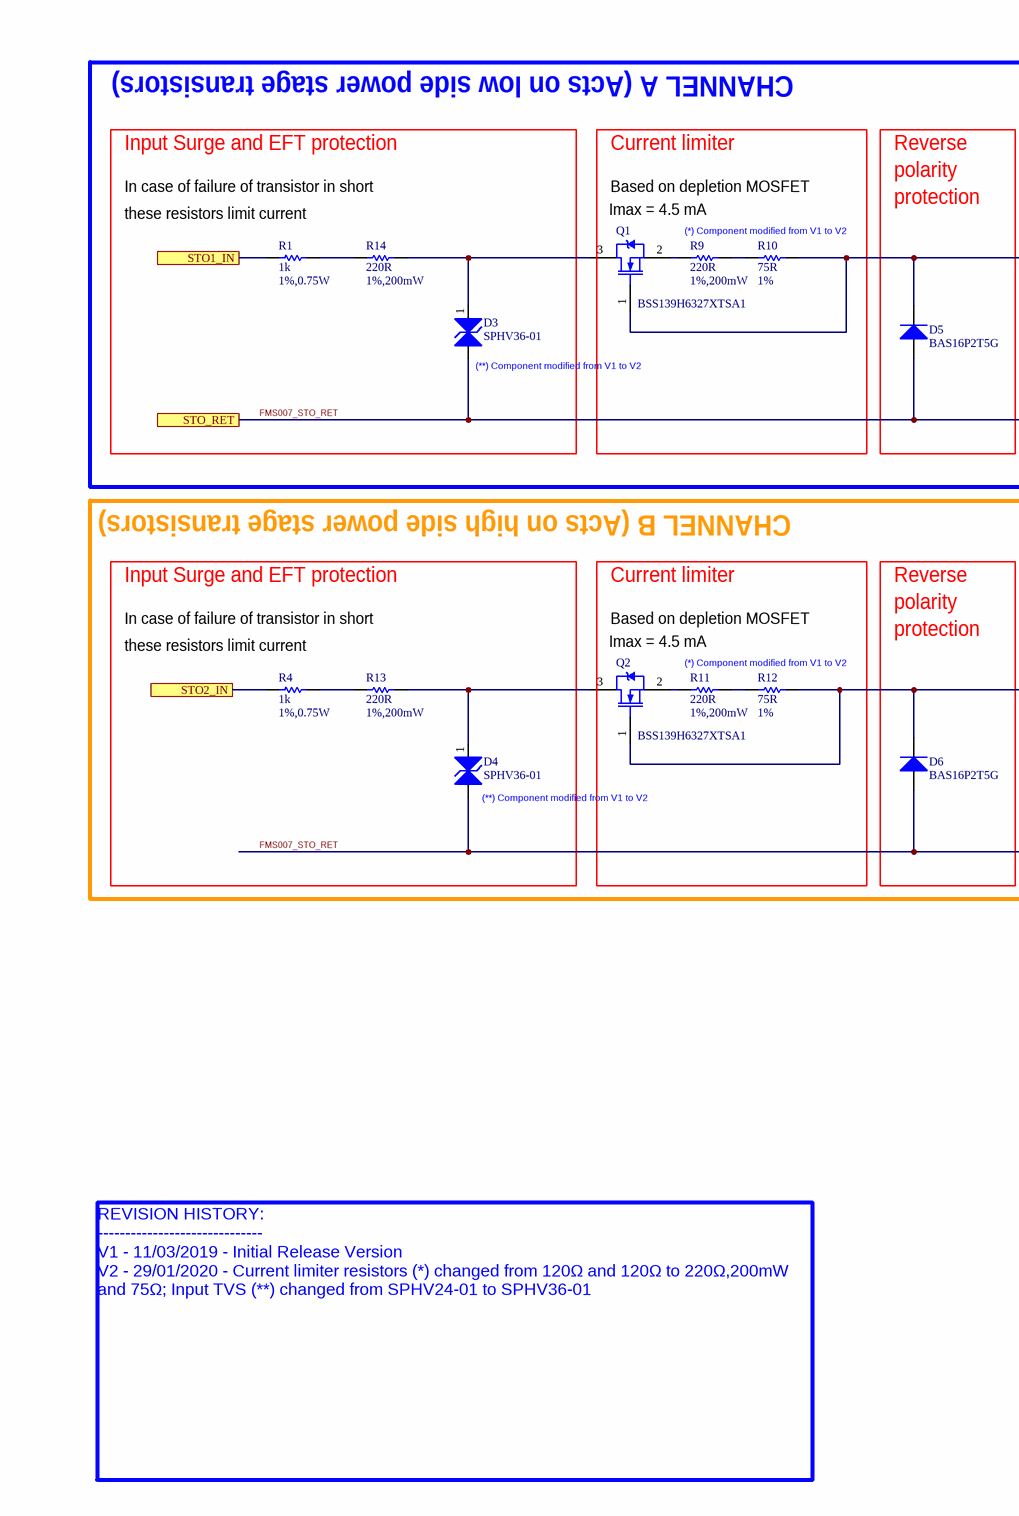
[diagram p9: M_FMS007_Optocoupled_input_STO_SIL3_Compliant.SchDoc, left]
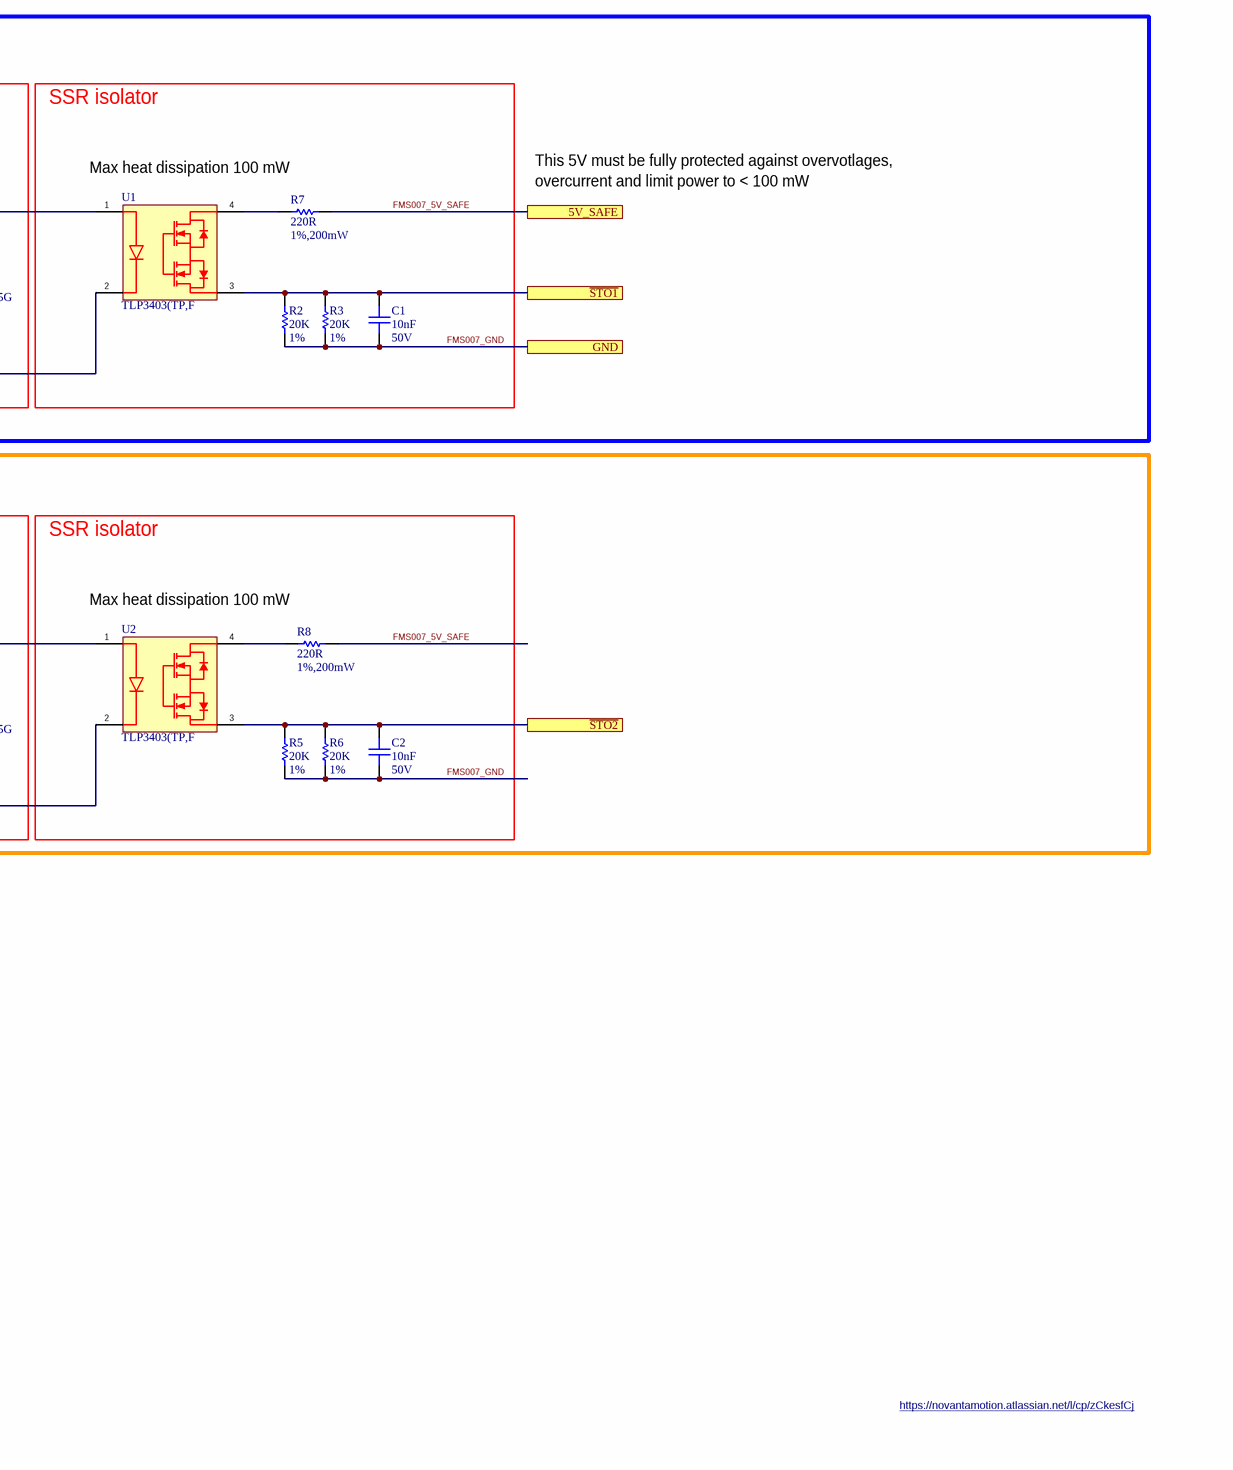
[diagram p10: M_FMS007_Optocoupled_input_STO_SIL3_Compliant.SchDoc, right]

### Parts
(Parts that share a designator on the sheet are numbered #1, #2 ... from top to bottom, then left to right.)
C1#6  value 10nF  Voltage: 50V  [C_0402HD]  (hidden comment: C_0402--10nF--50V)
C2#6  value 10nF  Voltage: 50V  [C_0402HD]  (hidden comment: C_0402--10nF--50V)
D3#2  SPHV36-01  [SOD-882]
D4#2  SPHV36-01  [SOD-882]
D5#2  BAS16P2T5G  [SOD923]
D6#2  BAS16P2T5G  [SOD923]
Q1#3  BSS139H6327XTSA1  [SOT23-3N]
Q2#3  BSS139H6327XTSA1  [SOT23-3N]
R1#3  value 1k  Tolerance: 1%,0.75W  [R_1206_HD]  (hidden comment: R_1206--1k--1%,0.75W)
R2#2  value 20K  Tolerance: 1%  [R_0402HD]  (hidden comment: R_0402--20K--1%)
R3#4  value 20K  Tolerance: 1%  [R_0402HD]  (hidden comment: R_0402--20K--1%)
R4#2  value 1k  Tolerance: 1%,0.75W  [R_1206_HD]  (hidden comment: R_1206--1k--1%,0.75W)
R5#3  value 20K  Tolerance: 1%  [R_0402HD]  (hidden comment: R_0402--20K--1%)
R6#3  value 20K  Tolerance: 1%  [R_0402HD]  (hidden comment: R_0402--20K--1%)
R7#4  value 220R  Tolerance: 1%,200mW  [R_0402HD]  (hidden comment: R_0402--220R--1%,200mW)
R8#2  value 220R  Tolerance: 1%,200mW  [R_0402HD]  (hidden comment: R_0402--220R--1%,200mW)
R9#2  value 220R  Tolerance: 1%,200mW  [R_0402HD]  (hidden comment: R_0402--220R--1%,200mW)
R10#2  value 75R  Tolerance: 1%  [R_0402HD]  (hidden comment: R_0402--75R--1%)
R11#3  value 220R  Tolerance: 1%,200mW  [R_0402HD]  (hidden comment: R_0402--220R--1%,200mW)
R12#2  value 75R  Tolerance: 1%  [R_0402HD]  (hidden comment: R_0402--75R--1%)
R13#2  value 220R  Tolerance: 1%,200mW  [R_0402HD]  (hidden comment: R_0402--220R--1%,200mW)
R14#2  value 220R  Tolerance: 1%,200mW  [R_0402HD]  (hidden comment: R_0402--220R--1%,200mW)
U1#6  TLP3403(TP,F  [4-VSON]
U2#3  TLP3403(TP,F  [4-VSON]

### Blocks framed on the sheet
CHANNEL A (Acts on low side power stage transistors): D5#2
Input Surge and EFT protection: D3#2 R1#3 R14#2
Current limiter: Q1#3 R9#2 R10#2
SSR isolator: C1#6 R2#2 R3#4 R7#4 U1#6
CHANNEL B (Acts on high side power stage transistors): D6#2
Input Surge and EFT protection: D4#2 R4#2 R13#2
Current limiter: Q2#3 R11#3 R12#2
SSR isolator: C2#6 R5#3 R6#3 R8#2 U2#3

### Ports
5V_SAFE, GND, STO1_IN, STO2_IN, STO_RET, ~{STO1}, ~{STO2}

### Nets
FMS007_GND: C1#6.2 C2#6.2 R2#2.2 R3#4.2 R5#3.2 R6#3.2 ; port GND  [project net GND_D]
~{STO1}: C1#6.1 R2#2.1 R3#4.1 U1#6.3(Drain1) ; port ~{STO1}
~{STO2}: C2#6.1 R5#3.1 R6#3.1 U2#3.3(Drain1) ; port ~{STO2}
FMS007_5V_SAFE: R7#4.2 R8#2.2 ; port 5V_SAFE  [project net 5V_SAFE]
FMS007_STO_RET: D3#2.2 D4#2.2 D5#2.1(A) D6#2.1(A) U1#6.2(Cathode) U2#3.2(Cathode) ; port STO_RET  [project net STO_RET]
STO1_IN: R1#3.1 ; port STO1_IN
STO2_IN: R4#2.1 ; port STO2_IN
NetD3#2_1: D3#2.1 Q1#3.3(D) R14#2.1
NetD4#2_1: D4#2.1 Q2#3.3(D) R13#2.1
NetD5#2_2: D5#2.2(K) Q1#3.1(G) R10#2.2 U1#6.1(Anode)
NetD6#2_2: D6#2.2(K) Q2#3.1(G) R12#2.2 U2#3.1(Anode)
NetQ1#3_2: Q1#3.2(S) R9#2.1
NetQ2#3_2: Q2#3.2(S) R11#3.1
NetR1#3_2: R1#3.2 R14#2.2
NetR4#2_2: R4#2.2 R13#2.2
NetR7#4_1: R7#4.1 U1#6.4(Drain2)
NetR8#2_1: R8#2.1 U2#3.4(Drain2)
NetR9#2_2: R9#2.2 R10#2.1
NetR11#3_2: R11#3.2 R12#2.1

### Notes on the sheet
- In case of failure of transistor in short
- Based on depletion MOSFET
- Reverse
- polarity
- these resistors limit current
- Imax = 4.5 mA
- (*) Component modified from V1 to V2
- protection
- Max heat dissipation 100 mW
- This 5V must be fully protected against overvotlages,
- overcurrent and limit power to < 100 mW
- (near D3#2) (**) Component modified from V1 to V2
- (near D4#2) (**) Component modified from V1 to V2
- REVISION HISTORY:
  ------------------------------
  V1 - 11/03/2019 - Initial Release Version
  V2 - 29/01/2020 - Current limiter resistors (*) changed from 120Ω and 120Ω to 220Ω,200mW and 75Ω; Input TVS (**) changed from SPHV24-01 to SPHV36-01
- https://novantamotion.atlassian.net/l/cp/zCkesfCj

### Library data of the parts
C1#6 C2#6 = C_0402[[/\]]10nF[[/\]]50V: CAP CER 10nF 50V X7R 0402; Part Number: C_0402; ManufacturerName: Samsung Electro-Mechanics; ManufacturerPN: CL05B103KB5NNNC; AlternativeManufacturer: KEMET; IsGeneric: 0; TemperatureMaxC: 125; TemperatureMinC: -55; AlternativePN: C0402C103K5RACTU
D3#2 D4#2 = SPHV36-01: TVS Diode Bidirectional 36V working, 65V clamping,2A (8/20µs), 200W pk; ManufacturerName: Littelfuse Inc.; ManufacturerPN: SPHV36-01ETG-C; Value: TVS 36V; IsGeneric: 0; TemperatureMaxC: 125; TemperatureMinC: -40; AlternativePN: AQHV36-01ETG-C
D5#2 D6#2 = BAS16P2T5G: Diode High Speed 100V 200mA SOD923; ManufacturerName: ON Semiconductor; AlternativeManufacturer: Central Semiconductor Corp; IsGeneric: 0; TemperatureMaxC: 150; TemperatureMinC: -55; AlternativePN: CMAD4448 TR
Q1#3 Q2#3 = BSS139H6327XTSA1: DEPLETION MOSFET N-CH 250V, 100mA, SOT23; ManufacturerName: Infineon; IsGeneric: 0; TemperatureMaxC: 150; TemperatureMinC: -55
R1#3 R4#2 = R_1206[[/\]]1k[[/\]]1%,0.75W: Resistor 1kohm 1% 750mW Pulse Withstanding 100ppm; Part Number: R_1206; ManufacturerName: Bourns Inc.; ManufacturerPN: CHP1206-FX-1001ELF; AlternativeManufacturer: Vishay Dale; IsGeneric: 0; TemperatureMaxC: 155; TemperatureMinC: -55; AlternativePN: RCA12061K00FKEAHP
R2#2 R3#4 R5#3 R6#3 = R_0402[[/\]]20K[[/\]]1%: RES 20K OHM 1/10W 1% 0402 SMD; Part Number: R_0402; ManufacturerName: Panasonic Electronic Components; ManufacturerPN: ERJ-2RKF2002X; AlternativeManufacturer: Vishay; IsGeneric: 1; TemperatureMaxC: 155; TemperatureMinC: -55; AlternativePN: CRCW040220K0FKED
R7#4 R8#2 R13#2 R14#2 = R_0402[[/\]]220R[[/\]]1%,200mW: Resistor 220ohm 200mW high power pulse withstanding; Part Number: R_0402; ManufacturerName: Panasonic Electronic Components; ManufacturerPN: ERJ-PA2F2200X; AlternativeManufacturer: VISHAY; IsGeneric: 1; AlternativePN: CRCW0402220RFKEDHP; TemperatureMaxC: 155; TemperatureMinC: -55
R9#2 R11#3 = R_0402[[/\]]220R[[/\]]1%,200mW: Resistor 220ohm 200mW high power pulse withstanding; Part Number: R_0402; ManufacturerName: Panasonic Electronic Components; ManufacturerPN: ERJ-PA2F2200X; AlternativeManufacturer: VISHAY; IsGeneric: 1; TemperatureMaxC: 155; TemperatureMinC: -55; AlternativePN: CRCW0402220RFKEDHP
R10#2 R12#2 = R_0402[[/\]]75R[[/\]]1%: as R1 on sheet M_IEA007_HDI_EtherNet_Discrete_Magnetics+ESD
U1#6 U2#3 = TLP3403(TP,F: SSR SPST-NO (1 Form A), 1A, 0~20V, 4-SMD 4-VSON (1.4mm height); ManufacturerName: Toshiba; IsGeneric: 0; TemperatureMaxC: 110; TemperatureMinC: -40

## Sheet M_GAI020_HD_Diff_In_Diff_Out+-10V_AnalogInput_3V3REF.SchDoc
size A4; Organization: Ingenia Drives - Novanta; Address1: Carrer Avila, 124, 2B; Address2: 08018 Barcelona Spain; Address3: www.ingeniamc.com; Address4: www.ingeniamc.com; DocumentNumber: 3; Revision: i044-01H6-1.2.3; SheetNumber: 3; SheetTotal: 8
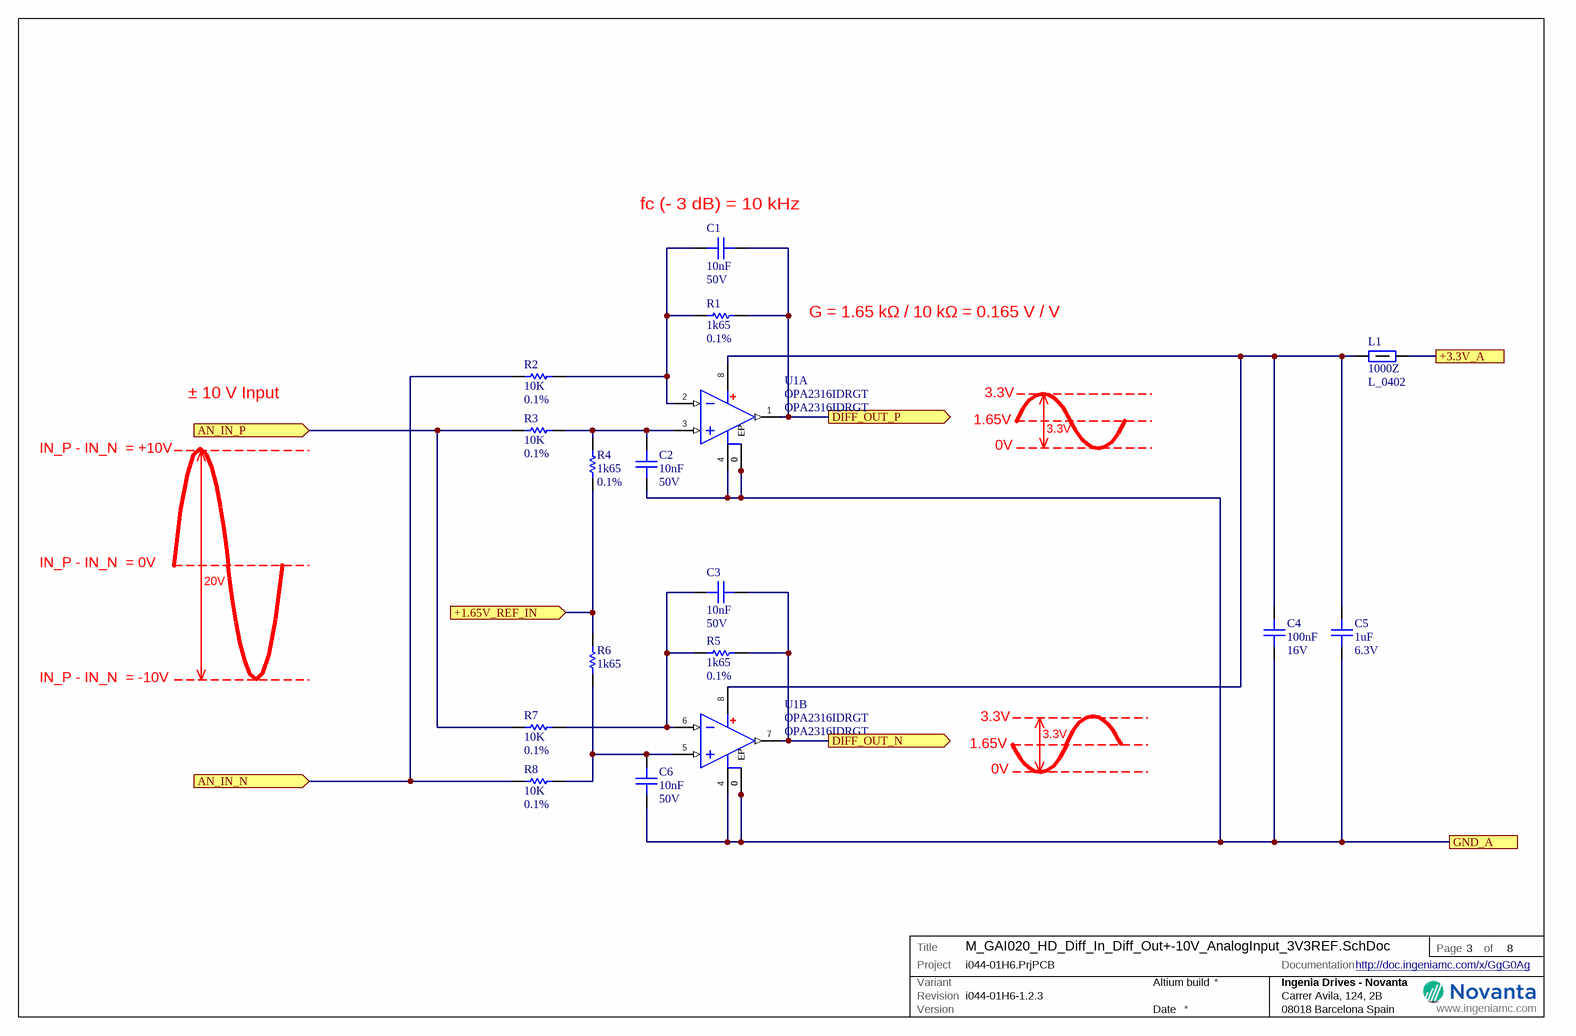
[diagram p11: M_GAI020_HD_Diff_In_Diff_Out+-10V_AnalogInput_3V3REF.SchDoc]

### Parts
(Parts that share a designator on the sheet are numbered #1, #2 ... from top to bottom, then left to right.)
C1#7  value 10nF  Voltage: 50V  [C_0402HD]  (hidden comment: C_0402--10nF--50V)
C2#7  value 10nF  Voltage: 50V  [C_0402HD]  (hidden comment: C_0402--10nF--50V)
C3#4  value 10nF  Voltage: 50V  [C_0402HD]  (hidden comment: C_0402--10nF--50V)
C4#4  value 100nF  Voltage: 16V  [C_0402HD]  (hidden comment: C_0402--100nF--16V)
C5#3  value 1uF  Voltage: 6.3V  [C_0402HD]  (hidden comment: C_0402--1uF--6.3V)
C6#3  value 10nF  Voltage: 50V  [C_0402HD]  (hidden comment: C_0402--10nF--50V)
L1#2  value 1000Z  [L_0402HD]  (hidden comment: L_0402)
R1#4  value 1k65  Tolerance: 0.1%  [R_0402HD]  (hidden comment: R_0402--1k65--0.1%)
R2#3  value 10K  Tolerance: 0.1%  [R_0402HD]  (hidden comment: R_0402--10K--0.1%)
R3#5  value 10K  Tolerance: 0.1%  [R_0402HD]  (hidden comment: R_0402--10K--0.1%)
R4#3  value 1k65  Tolerance: 0.1%  [R_0402HD]  (hidden comment: R_0402--1k65--0.1%)
R5#4  value 1k65  Tolerance: 0.1%  [R_0402HD]  (hidden comment: R_0402--1k65--0.1%)
R6#4  value 1k65  [R_0402HD]  (hidden comment: R_0402--1k65--0.1%)
R7#5  value 10K  Tolerance: 0.1%  [R_0402HD]  (hidden comment: R_0402--10K--0.1%)
R8#3  value 10K  Tolerance: 0.1%  [R_0402HD]  (hidden comment: R_0402--10K--0.1%)
U1#7  OPA2316IDRGT  [8-WFDFN]  (parts A,B of 2)

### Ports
+1.65V_REF_IN (in), +3.3V_A, AN_IN_N (in), AN_IN_P (in), DIFF_OUT_N (out), DIFF_OUT_P (out), GND_A

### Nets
GND_A: C2#7.2 C4#4.1 C5#3.1 C6#3.1 U1#7.0(EP) U1#7.4(VSS) ; port GND_A
1.65V_REF: R4#3.1 R6#4.2 ; port +1.65V_REF_IN
3.3V_D: L1#2.2 ; port +3.3V_A
AN1/AN_HALL_A/VOLT_C_N: C3#4.2 R5#4.2 U1#7.7(VOUTB) ; port DIFF_OUT_N
AN1/AN_HALL_A/VOLT_C_P: C1#7.2 R1#4.2 U1#7.1(VOUTA) ; port DIFF_OUT_P
AN1_N: R2#3.1 R8#3.2 ; port AN_IN_N
AN1_P: R3#5.2 R7#5.1 ; port AN_IN_P
NetC1#7_1: C1#7.1 R1#4.1 R2#3.2 U1#7.2(VINA-)
NetC2#7_1: C2#7.1 R3#5.1 R4#3.2 U1#7.3(VINA+)
NetC3#4_1: C3#4.1 R5#4.1 R7#5.2 U1#7.6(VINB-)
NetC4#4_2: C4#4.2 C5#3.2 L1#2.1 U1#7.8(VDD)
NetC6#3_2: C6#3.2 R6#4.1 R8#3.1 U1#7.5(VINB+)

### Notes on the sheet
- (near C1#7) fc (- 3 dB) = 10 kHz
- G = 1.65 kΩ / 10 kΩ = 0.165 V / V
- ± 10 V Input
- 1.65V
- 3.3V
- 0V
- IN_P - IN_N  = +10V
- IN_P - IN_N  = 0V
- 20V
- IN_P - IN_N  = -10V
- http://doc.ingeniamc.com/x/GgG0Ag

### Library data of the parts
C1#7 C2#7 C3#4 C6#3 = C_0402[[/\]]10nF[[/\]]50V: CAP CER 10nF 50V X7R 0402; Part Number: C_0402; ManufacturerName: KEMET; ManufacturerPN: C0402C103K5RACTU; AlternativeManufacturer: TDK Corporation; IsPreferred: 0; IngeniaID: 3723; TemperatureMaxC: 125; TemperatureMinC: -55; AlternativePN: C1005X8R1H103K050BB
C4#4 = C_0402[[/\]]100nF[[/\]]16V: as C13#2 on sheet M_SSD128_HD_8_95Vin_5Vout_1500mA_LowProfile
C5#3 = C_0402[[/\]]1uF[[/\]]6.3V: Capacitor 1uF 6.3V Ceramic X7S 0402; Part Number: C_0402; ManufacturerName: TDK Corporation; ManufacturerPN: CGB2A1X7S0J105M033BC; AlternativeManufacturer: Murata; IsPreferred: 0; IngeniaID: 4281; IsGeneric: 1; AlternativePN: GRM155R70J105KA12D; MTBF55h: 28045508; TemperatureMaxC: 125; TemperatureMinC: -55
L1#2 = L_0402[[/\]]1000Z: FERRITE BEAD, 0402 CASE, 200mA, Wideband; ManufacturerName: TDK; ManufacturerPN: MMZ1005S102CT000; AlternativeManufacturer: Murata; CompletePN: L_0402--1000Z; IsPreferred: 0; IsGeneric: 1; IngeniaID: 3897; TemperatureMaxC: 125; TemperatureMinC: -55; AlternativePN: BLM15BD102SN1D
R1#4 R4#3 R5#4 R6#4 = R_0402[[/\]]1k65[[/\]]0.1%: Reistor 1k65 1.65kohm 1/16W 0.1%; Part Number: R_0402; ManufacturerName: TE connectivity; ManufacturerPN: CPF0402B1K65E1; AlternativeManufacturer: Yageo; IsPreferred: 0; IngeniaID: 2176; IsGeneric: 1; TemperatureMaxC: 155; TemperatureMinC: -55; AlternativePN: RT0402BRD071K65L
R2#3 R3#5 R7#5 R8#3 = R_0402[[/\]]10K[[/\]]0.1%: RESISTOR, 0402 0,1% 10K 1/16W; Part Number: R_0402; ManufacturerName: Stackpole Electronics Inc.; ManufacturerPN: RNCF0402BTE10K0; AlternativeManufacturer: Susumu; IsPreferred: 0; IngeniaID: 1282; IsGeneric: 1; MTBF55h: 91649788; TemperatureMaxC: 155; TemperatureMinC: -55; AlternativePN: RG1005P-103-B-T5
U1#7 = OPA2316IDRGT: OP AMP, R-R, DUAL, 10 MHz; ManufacturerName: Texas Instruments; IsPreferred: 0; IngeniaID: 4250; TemperatureMaxC: 125; TemperatureMinC: -40; AlternativePN: OPA2316IDRGR

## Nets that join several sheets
5V_D: Top (20 pins), M_ICA011_HDI_CAN_Interface_NonIsolated_5Vsupply (C1#3.2 U1#3.3), M_PXE032_HD_Diff-SE_Digital_Abs_Encoder_WBias_WTerm (10 pins), M_PXA001_HDI_BiSS_SSI_EnDAT_AbsoluteEncoder (RN1#2.1 RN1#2.3 RN1#2.5)
5V_DCDC: Top (C19#1.2 L5.1), M_SSD128_HD_8_95Vin_5Vout_1500mA_LowProfile (7 pins)
+LOGIC_DCDC: Top (L1#1.2), M_SSD128_HD_8_95Vin_5Vout_1500mA_LowProfile (14 pins)
GND_A: Top (15 pins), M_GAI020_HD_Diff_In_Diff_Out+-10V_AnalogInput_3V3REF (6 pins)
GND_D: Top (101 pins), M_ICA011_HDI_CAN_Interface_NonIsolated_5Vsupply (5 pins), M_PXE032_HD_Diff-SE_Digital_Abs_Encoder_WBias_WTerm (11 pins), U_M_IEA007_EHT0 (C1_U_M_IEA007_EHT0.1 C2_U_M_IEA007_EHT0.2 C4_U_M_IEA007_EHT0.2), U_M_IEA007_EHT1 (C1_U_M_IEA007_EHT1.1 C2_U_M_IEA007_EHT1.2 C4_U_M_IEA007_EHT1.2), M_PXA001_HDI_BiSS_SSI_EnDAT_AbsoluteEncoder (7 pins), M_FMS007_Optocoupled_input_STO_SIL3_Compliant (6 pins)
GND_DCDC: Top (C19#1.1 L2#1.2 L6.1 P11.S1), M_SSD128_HD_8_95Vin_5Vout_1500mA_LowProfile (21 pins)
PE: Top (H1.1 M2.1 P6.5 P6.S1), U_M_IEA007_EHT1 (C5_U_M_IEA007_EHT1.1)
PE1: Top (M1.1 P3.5 P3.S2 P10.S1), U_M_IEA007_EHT0 (C5_U_M_IEA007_EHT0.1)
1.65V_REF: Top (P10.4), M_GAI020_HD_Diff_In_Diff_Out+-10V_AnalogInput_3V3REF (R4#3.1 R6#4.2)
3.3V_D: Top (8 pins), M_ICA011_HDI_CAN_Interface_NonIsolated_5Vsupply (C2#3.2 U1#3.5), M_PXE032_HD_Diff-SE_Digital_Abs_Encoder_WBias_WTerm (6 pins), M_PXA001_HDI_BiSS_SSI_EnDAT_AbsoluteEncoder (5 pins), M_GAI020_HD_Diff_In_Diff_Out+-10V_AnalogInput_3V3REF (L1#2.2)
5V_SAFE: Top (U4.A3 U4.B2 U4.B3), M_FMS007_Optocoupled_input_STO_SIL3_Compliant (R7#4.2 R8#2.2)
~{ABSENC1_CS}: Top (P11.31 U3#1.C2), M_PXA001_HDI_BiSS_SSI_EnDAT_AbsoluteEncoder (U5.2)
~{STO1}: Top (P10.33), M_FMS007_Optocoupled_input_STO_SIL3_Compliant (C1#6.1 R2#2.1 R3#4.1 U1#6.3)
~{STO2}: Top (P10.34), M_FMS007_Optocoupled_input_STO_SIL3_Compliant (C2#6.1 R5#3.1 R6#3.1 U2#3.3)
ABS2_CS: Top (U3#1.D2), M_PXE032_HD_Diff-SE_Digital_Abs_Encoder_WBias_WTerm (U3#2.2 U3#2.3)
ABS_SPI_CS: Top (U3#1.B1), M_PXA001_HDI_BiSS_SSI_EnDAT_AbsoluteEncoder (U1#5.3)
ABS_TX_EN: Top (P11.33 RN5.1), M_PXA001_HDI_BiSS_SSI_EnDAT_AbsoluteEncoder (U5.3)
ABSENC1_CLK: Top (P11.38), M_PXA001_HDI_BiSS_SSI_EnDAT_AbsoluteEncoder (U1#5.4)
ABSENC1_MISO: Top (P11.42), M_PXA001_HDI_BiSS_SSI_EnDAT_AbsoluteEncoder (U5.4)
ABSENC1_MOSI: Top (P11.40), M_PXA001_HDI_BiSS_SSI_EnDAT_AbsoluteEncoder (U5.1)
ABSENC2_CLK: Top (P10.24), M_PXE032_HD_Diff-SE_Digital_Abs_Encoder_WBias_WTerm (U3#2.4)
ABSENC2_MISO/DIGENC_1A: Top (P10.25 P11.24), M_PXE032_HD_Diff-SE_Digital_Abs_Encoder_WBias_WTerm (U1#4.3)
ABSENC_CLK_N: Top (D3#1.5 P5.19), M_PXA001_HDI_BiSS_SSI_EnDAT_AbsoluteEncoder (U1#5.7)
ABSENC_CLK_P: Top (D7.5 P5.17), M_PXA001_HDI_BiSS_SSI_EnDAT_AbsoluteEncoder (U1#5.6)
ABSENC_DATA_N: Top (D4#1.5 P5.18), M_PXA001_HDI_BiSS_SSI_EnDAT_AbsoluteEncoder (R15#2.2 RN1#2.6 RN1#2.8 U5.7)
ABSENC_DATA_P: Top (D4#1.4 P5.16), M_PXA001_HDI_BiSS_SSI_EnDAT_AbsoluteEncoder (R15#2.1 RN1#2.2 RN1#2.4 U5.6)
AN1/AN_HALL_A/VOLT_C_N: Top (P11.6), M_GAI020_HD_Diff_In_Diff_Out+-10V_AnalogInput_3V3REF (C3#4.2 R5#4.2 U1#7.7)
AN1/AN_HALL_A/VOLT_C_P: Top (P11.4), M_GAI020_HD_Diff_In_Diff_Out+-10V_AnalogInput_3V3REF (C1#7.2 R1#4.2 U1#7.1)
AN1_N: Top (P4.24 R7#1.2), M_GAI020_HD_Diff_In_Diff_Out+-10V_AnalogInput_3V3REF (R2#3.1 R8#3.2)
AN1_P: Top (P4.22 R1714.2), M_GAI020_HD_Diff_In_Diff_Out+-10V_AnalogInput_3V3REF (R3#5.2 R7#5.1)
CAN_COCO_RX: Top (P10.57), M_ICA011_HDI_CAN_Interface_NonIsolated_5Vsupply (U1#3.4)
CAN_COCO_TX: Top (P10.55 R12#1.2), M_ICA011_HDI_CAN_Interface_NonIsolated_5Vsupply (U1#3.1)
CANH: Top (D9.1 P4.9), M_ICA011_HDI_CAN_Interface_NonIsolated_5Vsupply (U1#3.7)
CANL: Top (D5#1.1 P4.11), M_ICA011_HDI_CAN_Interface_NonIsolated_5Vsupply (U1#3.6)
DIG_ENC_1B: Top (P11.26), M_PXE032_HD_Diff-SE_Digital_Abs_Encoder_WBias_WTerm (U2#2.3)
DIG_ENC_1C/AN_ENC_1C: Top (P11.28), M_PXE032_HD_Diff-SE_Digital_Abs_Encoder_WBias_WTerm (U3#2.1)
ENC_A/DATA_IN_N: Top (D7.3 P5.5), M_PXE032_HD_Diff-SE_Digital_Abs_Encoder_WBias_WTerm (R3#3.1 RN1#1.5 RN1#1.7 U1#4.4)
ENC_A/DATA_IN_P: Top (D13.4 P5.3), M_PXE032_HD_Diff-SE_Digital_Abs_Encoder_WBias_WTerm (R3#3.2 RN1#1.1 RN1#1.3 U1#4.5)
ENC_B_IN_N: Top (D3#1.3 P5.6), M_PXE032_HD_Diff-SE_Digital_Abs_Encoder_WBias_WTerm (R7#3.1 RN3#2.1 RN3#2.3 U2#2.4)
ENC_B_IN_P: Top (D7.4 P5.4), M_PXE032_HD_Diff-SE_Digital_Abs_Encoder_WBias_WTerm (R7#3.2 RN3#2.5 RN3#2.7 U2#2.5)
ENC_Z_IN/CLK_OUT_N: Top (D4#1.6 P5.8), M_PXE032_HD_Diff-SE_Digital_Abs_Encoder_WBias_WTerm (R11#2.2 RN2#2.1 RN2#2.3 U3#2.7)
ENC_Z_IN/CLK_OUT_P: Top (D3#1.4 P5.7), M_PXE032_HD_Diff-SE_Digital_Abs_Encoder_WBias_WTerm (R11#2.1 RN2#2.5 RN2#2.7 U3#2.6)
ETH0_RX_N: Top (P3.4), U_M_IEA007_EHT0 (L1_U_M_IEA007_EHT0.1)
ETH0_RX_P: Top (P3.3), U_M_IEA007_EHT0 (L1_U_M_IEA007_EHT0.2)
ETH0_TX_N: Top (P3.2), U_M_IEA007_EHT0 (L2_U_M_IEA007_EHT0.1)
ETH0_TX_P: Top (P3.1), U_M_IEA007_EHT0 (L2_U_M_IEA007_EHT0.2)
ETH1_RX_N: Top (P6.4), U_M_IEA007_EHT1 (L1_U_M_IEA007_EHT1.1)
ETH1_RX_P: Top (P6.3), U_M_IEA007_EHT1 (L1_U_M_IEA007_EHT1.2)
ETH1_TX_N: Top (P6.2), U_M_IEA007_EHT1 (L2_U_M_IEA007_EHT1.1)
ETH1_TX_P: Top (P6.1), U_M_IEA007_EHT1 (L2_U_M_IEA007_EHT1.2)
MAGNETICS_CT: Top (D20.5 D21.5 P10.13), U_M_IEA007_EHT0 (5 pins), U_M_IEA007_EHT1 (5 pins)
PHY0_RX_N: Top (D21.1 P10.77), U_M_IEA007_EHT0 (T1_U_M_IEA007_EHT0.1)
PHY0_RX_P: Top (D21.3 P10.75), U_M_IEA007_EHT0 (T1_U_M_IEA007_EHT0.2)
PHY0_TX_N: Top (D21.7 P10.73), U_M_IEA007_EHT0 (T2_U_M_IEA007_EHT0.1)
PHY0_TX_P: Top (D21.9 P10.71), U_M_IEA007_EHT0 (T2_U_M_IEA007_EHT0.2)
PHY1_RX_N: Top (D20.9 P10.78), U_M_IEA007_EHT1 (T1_U_M_IEA007_EHT1.1)
PHY1_RX_P: Top (D20.7 P10.76), U_M_IEA007_EHT1 (T1_U_M_IEA007_EHT1.2)
PHY1_TX_N: Top (D20.1 P10.74), U_M_IEA007_EHT1 (T2_U_M_IEA007_EHT1.1)
PHY1_TX_P: Top (D20.3 P10.72), U_M_IEA007_EHT1 (T2_U_M_IEA007_EHT1.2)
STO1_IN: Top (P4.1), M_FMS007_Optocoupled_input_STO_SIL3_Compliant (R1#3.1)
STO2_IN: Top (P4.5), M_FMS007_Optocoupled_input_STO_SIL3_Compliant (R4#2.1)
STO_RET: Top (P4.3), M_FMS007_Optocoupled_input_STO_SIL3_Compliant (6 pins)

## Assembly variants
BASIC: not fitted R57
